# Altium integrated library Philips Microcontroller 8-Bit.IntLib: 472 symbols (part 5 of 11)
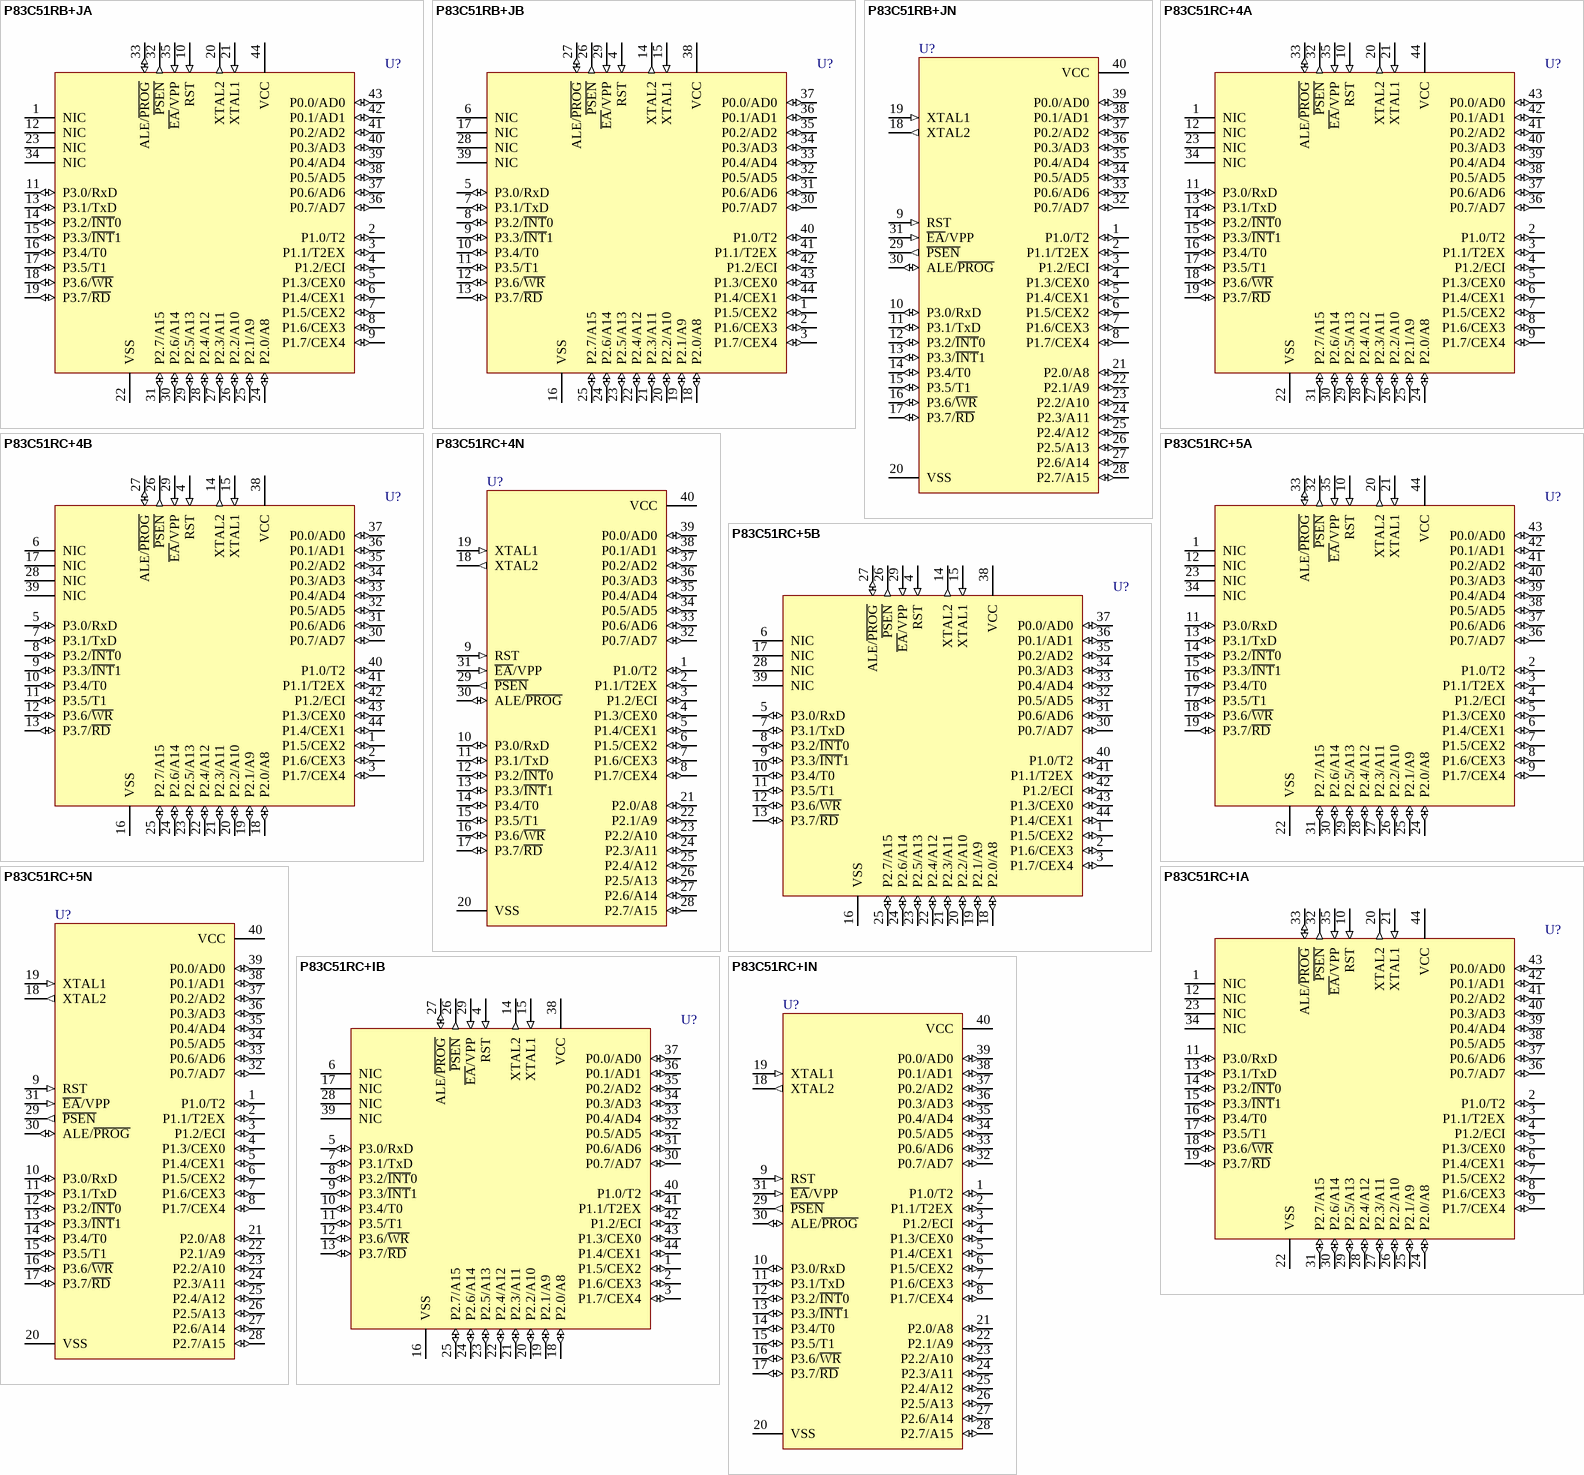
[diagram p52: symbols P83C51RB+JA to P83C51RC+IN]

## P83C51RC+IB
designator U?
80C51 8-Bit Microcontroller Family: 512 B RAM, 32 kB ROM, 5V, Low Power, High Speed
footprint SOT307-2_N (QFP, 44-Leads, Body 10x10mm, Pitch 0.8mm, IPC Medium Density)
footprint SOT307-2_L (QFP, 44-Leads, Body 10x10mm, Pitch 0.8mm, IPC High Density)
footprint SOT307-2_M (QFP, 44-Leads, Body 10x10mm, Pitch 0.8mm, IPC Low Density)
pins: 1 P1.5/CEX2 (io), 2 P1.6/CEX3 (io), 3 P1.7/CEX4 (io), 4 RST (in), 5 P3.0/RxD (io), 6 NIC, 7 P3.1/TxD (io), 8 P3.2/~{INT}0 (io), 9 P3.3/~{INT}1 (io), 10 P3.4/T0 (io), 11 P3.5/T1 (io), 12 P3.6/~{WR} (io), 13 P3.7/~{RD} (io), 14 XTAL2 (out), 15 XTAL1 (in), 16 VSS (power), 17 NIC, 18 P2.0/A8 (io), 19 P2.1/A9 (io), 20 P2.2/A10 (io), 21 P2.3/A11 (io), 22 P2.4/A12 (io), 23 P2.5/A13 (io), 24 P2.6/A14 (io), 25 P2.7/A15 (io), 26 ~{PSEN} (out), 27 ALE/~{PROG} (io), 28 NIC, 29 ~{EA}/VPP (in), 30 P0.7/AD7 (io), 31 P0.6/AD6 (io), 32 P0.5/AD5 (io), 33 P0.4/AD4 (io), 34 P0.3/AD3 (io), 35 P0.2/AD2 (io), 36 P0.1/AD1 (io), 37 P0.0/AD0 (io), 38 VCC (power), 39 NIC, 40 P1.0/T2 (io), 41 P1.1/T2EX (io), 42 P1.2/ECI (io), 43 P1.3/CEX0 (io), 44 P1.4/CEX1 (io)

## P83C51RC+IN
designator U?
80C51 8-Bit Microcontroller Family: 512 B RAM, 32 kB ROM, 5V, Low Power, High Speed
footprint SOT129-1 (DIP, Plastic; 40 Leads; Row Spacing 15.24 mm; Pitch 2.54 mm)
pins: 1 P1.0/T2 (io), 2 P1.1/T2EX (io), 3 P1.2/ECI (io), 4 P1.3/CEX0 (io), 5 P1.4/CEX1 (io), 6 P1.5/CEX2 (io), 7 P1.6/CEX3 (io), 8 P1.7/CEX4 (io), 9 RST (in), 10 P3.0/RxD (io), 11 P3.1/TxD (io), 12 P3.2/~{INT}0 (io), 13 P3.3/~{INT}1 (io), 14 P3.4/T0 (io), 15 P3.5/T1 (io), 16 P3.6/~{WR} (io), 17 P3.7/~{RD} (io), 18 XTAL2 (out), 19 XTAL1 (in), 20 VSS (power), 21 P2.0/A8 (io), 22 P2.1/A9 (io), 23 P2.2/A10 (io), 24 P2.3/A11 (io), 25 P2.4/A12 (io), 26 P2.5/A13 (io), 27 P2.6/A14 (io), 28 P2.7/A15 (io), 29 ~{PSEN} (out), 30 ALE/~{PROG} (io), 31 ~{EA}/VPP (in), 32 P0.7/AD7 (io), 33 P0.6/AD6 (io), 34 P0.5/AD5 (io), 35 P0.4/AD4 (io), 36 P0.3/AD3 (io), 37 P0.2/AD2 (io), 38 P0.1/AD1 (io), 39 P0.0/AD0 (io), 40 VCC (power)

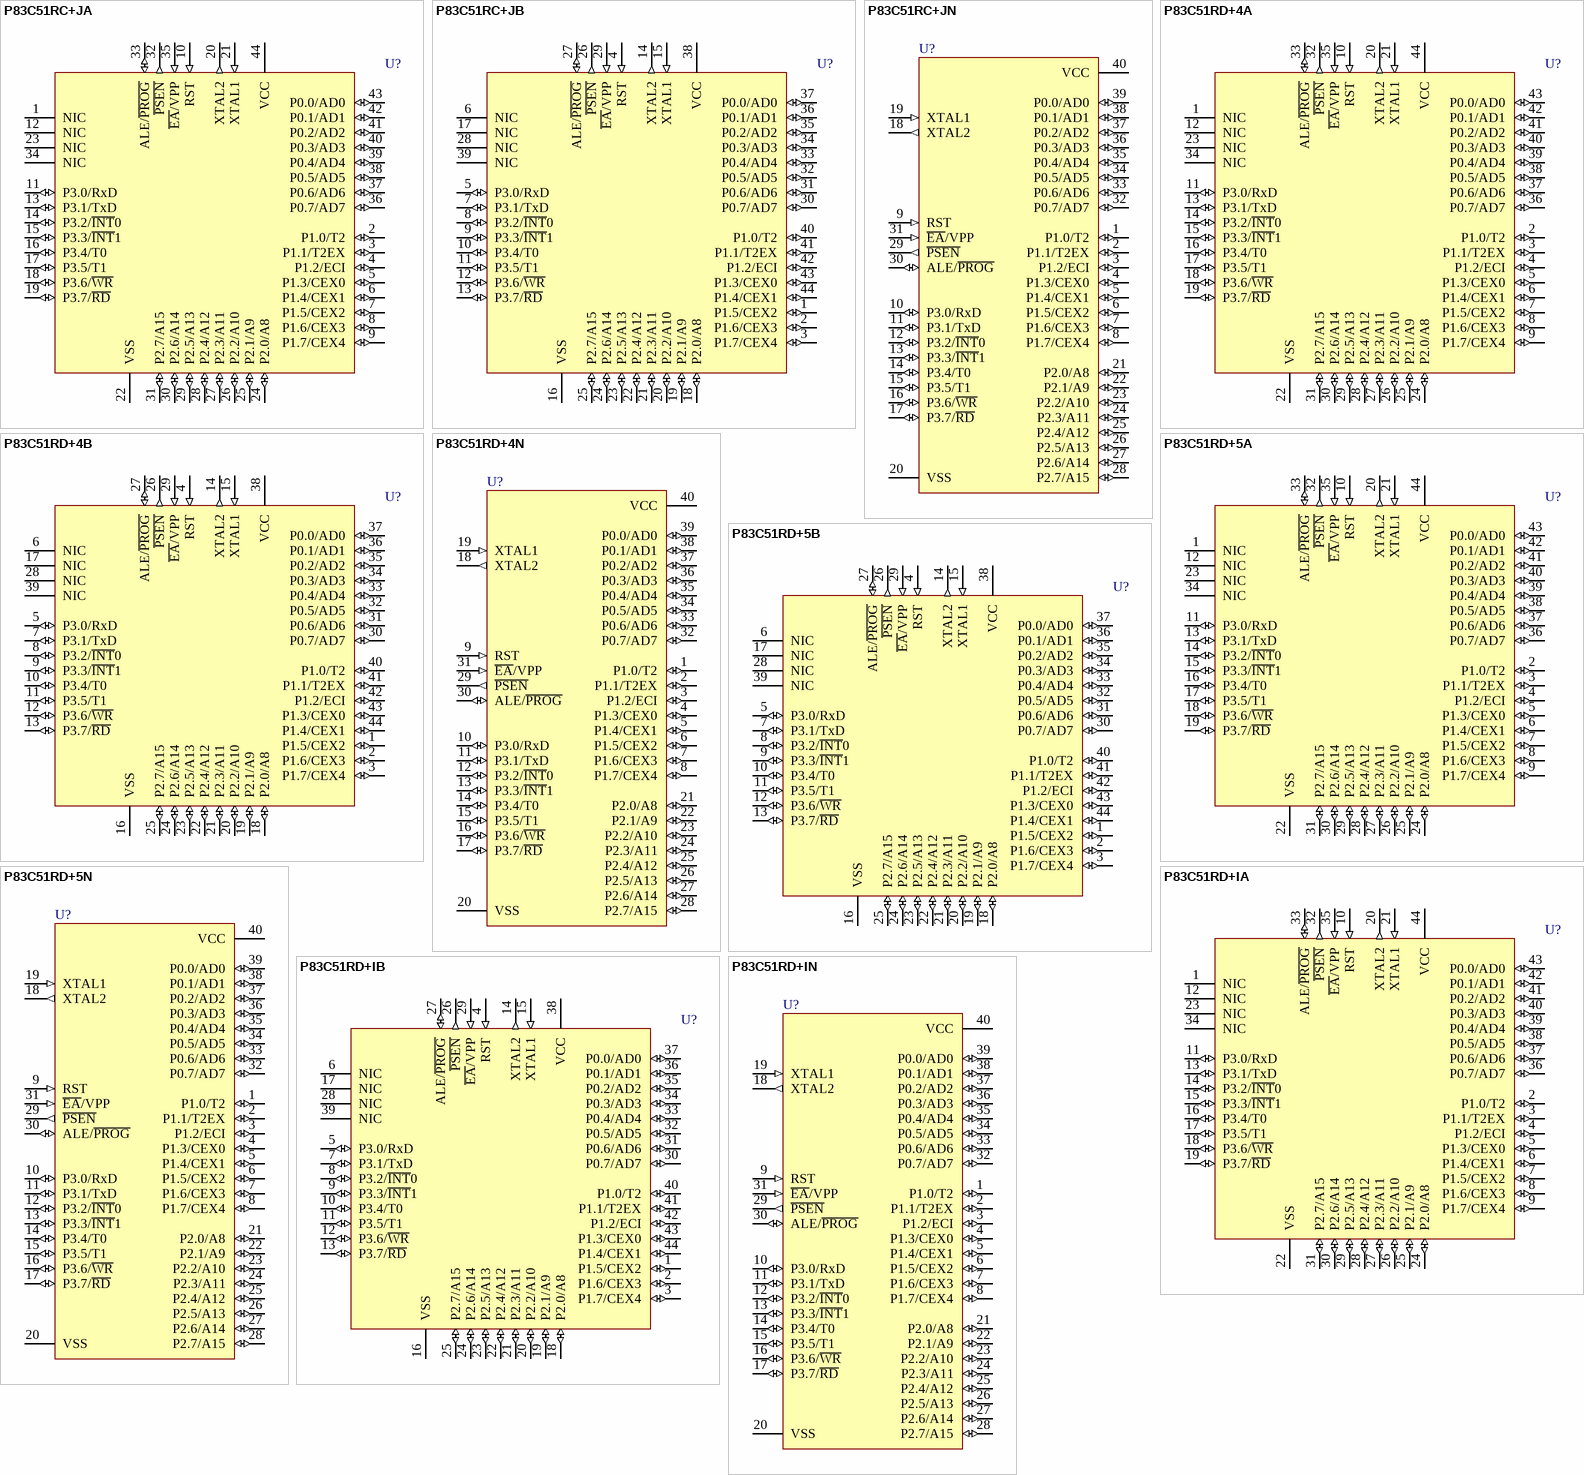
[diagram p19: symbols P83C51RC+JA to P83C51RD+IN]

## P83C51RC+JA
designator U?
80C51 8-Bit Microcontroller Family: 512 B RAM, 32 kB ROM, 5V, Low Power, High Speed
footprint SOT187-2_N (Leaded Chip Carrier, 44-Leads, Body 16.6x16.6mm, Pitch 1.27mm, IPC Medium Density)
footprint SOT187-2_L (Leaded Chip Carrier, 44-Leads, Body 16.6x16.6mm, Pitch 1.27mm, IPC High Density)
footprint SOT187-2_M (Leaded Chip Carrier, 44-Leads, Body 16.6x16.6mm, Pitch 1.27mm, IPC Low Density)
pins: 1 NIC, 2 P1.0/T2 (io), 3 P1.1/T2EX (io), 4 P1.2/ECI (io), 5 P1.3/CEX0 (io), 6 P1.4/CEX1 (io), 7 P1.5/CEX2 (io), 8 P1.6/CEX3 (io), 9 P1.7/CEX4 (io), 10 RST (in), 11 P3.0/RxD (io), 12 NIC, 13 P3.1/TxD (io), 14 P3.2/~{INT}0 (io), 15 P3.3/~{INT}1 (io), 16 P3.4/T0 (io), 17 P3.5/T1 (io), 18 P3.6/~{WR} (io), 19 P3.7/~{RD} (io), 20 XTAL2 (out), 21 XTAL1 (in), 22 VSS (power), 23 NIC, 24 P2.0/A8 (io), 25 P2.1/A9 (io), 26 P2.2/A10 (io), 27 P2.3/A11 (io), 28 P2.4/A12 (io), 29 P2.5/A13 (io), 30 P2.6/A14 (io), 31 P2.7/A15 (io), 32 ~{PSEN} (out), 33 ALE/~{PROG} (io), 34 NIC, 35 ~{EA}/VPP (in), 36 P0.7/AD7 (io), 37 P0.6/AD6 (io), 38 P0.5/AD5 (io), 39 P0.4/AD4 (io), 40 P0.3/AD3 (io), 41 P0.2/AD2 (io), 42 P0.1/AD1 (io), 43 P0.0/AD0 (io), 44 VCC (power)

## P83C51RC+JB
designator U?
80C51 8-Bit Microcontroller Family: 512 B RAM, 32 kB ROM, 5V, Low Power, High Speed
footprint SOT307-2_N (QFP, 44-Leads, Body 10x10mm, Pitch 0.8mm, IPC Medium Density)
footprint SOT307-2_L (QFP, 44-Leads, Body 10x10mm, Pitch 0.8mm, IPC High Density)
footprint SOT307-2_M (QFP, 44-Leads, Body 10x10mm, Pitch 0.8mm, IPC Low Density)
pins: 1 P1.5/CEX2 (io), 2 P1.6/CEX3 (io), 3 P1.7/CEX4 (io), 4 RST (in), 5 P3.0/RxD (io), 6 NIC, 7 P3.1/TxD (io), 8 P3.2/~{INT}0 (io), 9 P3.3/~{INT}1 (io), 10 P3.4/T0 (io), 11 P3.5/T1 (io), 12 P3.6/~{WR} (io), 13 P3.7/~{RD} (io), 14 XTAL2 (out), 15 XTAL1 (in), 16 VSS (power), 17 NIC, 18 P2.0/A8 (io), 19 P2.1/A9 (io), 20 P2.2/A10 (io), 21 P2.3/A11 (io), 22 P2.4/A12 (io), 23 P2.5/A13 (io), 24 P2.6/A14 (io), 25 P2.7/A15 (io), 26 ~{PSEN} (out), 27 ALE/~{PROG} (io), 28 NIC, 29 ~{EA}/VPP (in), 30 P0.7/AD7 (io), 31 P0.6/AD6 (io), 32 P0.5/AD5 (io), 33 P0.4/AD4 (io), 34 P0.3/AD3 (io), 35 P0.2/AD2 (io), 36 P0.1/AD1 (io), 37 P0.0/AD0 (io), 38 VCC (power), 39 NIC, 40 P1.0/T2 (io), 41 P1.1/T2EX (io), 42 P1.2/ECI (io), 43 P1.3/CEX0 (io), 44 P1.4/CEX1 (io)

## P83C51RC+JN
designator U?
80C51 8-Bit Microcontroller Family: 512 B RAM, 32 kB ROM, 5V, Low Power, High Speed
footprint SOT129-1 (DIP, Plastic; 40 Leads; Row Spacing 15.24 mm; Pitch 2.54 mm)
pins: 1 P1.0/T2 (io), 2 P1.1/T2EX (io), 3 P1.2/ECI (io), 4 P1.3/CEX0 (io), 5 P1.4/CEX1 (io), 6 P1.5/CEX2 (io), 7 P1.6/CEX3 (io), 8 P1.7/CEX4 (io), 9 RST (in), 10 P3.0/RxD (io), 11 P3.1/TxD (io), 12 P3.2/~{INT}0 (io), 13 P3.3/~{INT}1 (io), 14 P3.4/T0 (io), 15 P3.5/T1 (io), 16 P3.6/~{WR} (io), 17 P3.7/~{RD} (io), 18 XTAL2 (out), 19 XTAL1 (in), 20 VSS (power), 21 P2.0/A8 (io), 22 P2.1/A9 (io), 23 P2.2/A10 (io), 24 P2.3/A11 (io), 25 P2.4/A12 (io), 26 P2.5/A13 (io), 27 P2.6/A14 (io), 28 P2.7/A15 (io), 29 ~{PSEN} (out), 30 ALE/~{PROG} (io), 31 ~{EA}/VPP (in), 32 P0.7/AD7 (io), 33 P0.6/AD6 (io), 34 P0.5/AD5 (io), 35 P0.4/AD4 (io), 36 P0.3/AD3 (io), 37 P0.2/AD2 (io), 38 P0.1/AD1 (io), 39 P0.0/AD0 (io), 40 VCC (power)

## P83C51RD+4A
designator U?
80C51 8-Bit Microcontroller Family: 1 kB RAM, 64 kB ROM, 2.7V-5.5V, Low Power, High Speed
footprint SOT187-2_N (Leaded Chip Carrier, 44-Leads, Body 16.6x16.6mm, Pitch 1.27mm, IPC Medium Density)
footprint SOT187-2_L (Leaded Chip Carrier, 44-Leads, Body 16.6x16.6mm, Pitch 1.27mm, IPC High Density)
footprint SOT187-2_M (Leaded Chip Carrier, 44-Leads, Body 16.6x16.6mm, Pitch 1.27mm, IPC Low Density)
pins: 1 NIC, 2 P1.0/T2 (io), 3 P1.1/T2EX (io), 4 P1.2/ECI (io), 5 P1.3/CEX0 (io), 6 P1.4/CEX1 (io), 7 P1.5/CEX2 (io), 8 P1.6/CEX3 (io), 9 P1.7/CEX4 (io), 10 RST (in), 11 P3.0/RxD (io), 12 NIC, 13 P3.1/TxD (io), 14 P3.2/~{INT}0 (io), 15 P3.3/~{INT}1 (io), 16 P3.4/T0 (io), 17 P3.5/T1 (io), 18 P3.6/~{WR} (io), 19 P3.7/~{RD} (io), 20 XTAL2 (out), 21 XTAL1 (in), 22 VSS (power), 23 NIC, 24 P2.0/A8 (io), 25 P2.1/A9 (io), 26 P2.2/A10 (io), 27 P2.3/A11 (io), 28 P2.4/A12 (io), 29 P2.5/A13 (io), 30 P2.6/A14 (io), 31 P2.7/A15 (io), 32 ~{PSEN} (out), 33 ALE/~{PROG} (io), 34 NIC, 35 ~{EA}/VPP (in), 36 P0.7/AD7 (io), 37 P0.6/AD6 (io), 38 P0.5/AD5 (io), 39 P0.4/AD4 (io), 40 P0.3/AD3 (io), 41 P0.2/AD2 (io), 42 P0.1/AD1 (io), 43 P0.0/AD0 (io), 44 VCC (power)

## P83C51RD+4B
designator U?
80C51 8-Bit Microcontroller Family: 1 kB RAM, 64 kB ROM, 2.7V-5.5V, Low Power, High Speed
footprint SOT307-2_N (QFP, 44-Leads, Body 10x10mm, Pitch 0.8mm, IPC Medium Density)
footprint SOT307-2_L (QFP, 44-Leads, Body 10x10mm, Pitch 0.8mm, IPC High Density)
footprint SOT307-2_M (QFP, 44-Leads, Body 10x10mm, Pitch 0.8mm, IPC Low Density)
pins: 1 P1.5/CEX2 (io), 2 P1.6/CEX3 (io), 3 P1.7/CEX4 (io), 4 RST (in), 5 P3.0/RxD (io), 6 NIC, 7 P3.1/TxD (io), 8 P3.2/~{INT}0 (io), 9 P3.3/~{INT}1 (io), 10 P3.4/T0 (io), 11 P3.5/T1 (io), 12 P3.6/~{WR} (io), 13 P3.7/~{RD} (io), 14 XTAL2 (out), 15 XTAL1 (in), 16 VSS (power), 17 NIC, 18 P2.0/A8 (io), 19 P2.1/A9 (io), 20 P2.2/A10 (io), 21 P2.3/A11 (io), 22 P2.4/A12 (io), 23 P2.5/A13 (io), 24 P2.6/A14 (io), 25 P2.7/A15 (io), 26 ~{PSEN} (out), 27 ALE/~{PROG} (io), 28 NIC, 29 ~{EA}/VPP (in), 30 P0.7/AD7 (io), 31 P0.6/AD6 (io), 32 P0.5/AD5 (io), 33 P0.4/AD4 (io), 34 P0.3/AD3 (io), 35 P0.2/AD2 (io), 36 P0.1/AD1 (io), 37 P0.0/AD0 (io), 38 VCC (power), 39 NIC, 40 P1.0/T2 (io), 41 P1.1/T2EX (io), 42 P1.2/ECI (io), 43 P1.3/CEX0 (io), 44 P1.4/CEX1 (io)

## P83C51RD+4N
designator U?
80C51 8-Bit Microcontroller Family: 1 kB RAM, 64 kB ROM, 2.7V-5.5V, Low Power, High Speed
footprint SOT129-1 (DIP, Plastic; 40 Leads; Row Spacing 15.24 mm; Pitch 2.54 mm)
pins: 1 P1.0/T2 (io), 2 P1.1/T2EX (io), 3 P1.2/ECI (io), 4 P1.3/CEX0 (io), 5 P1.4/CEX1 (io), 6 P1.5/CEX2 (io), 7 P1.6/CEX3 (io), 8 P1.7/CEX4 (io), 9 RST (in), 10 P3.0/RxD (io), 11 P3.1/TxD (io), 12 P3.2/~{INT}0 (io), 13 P3.3/~{INT}1 (io), 14 P3.4/T0 (io), 15 P3.5/T1 (io), 16 P3.6/~{WR} (io), 17 P3.7/~{RD} (io), 18 XTAL2 (out), 19 XTAL1 (in), 20 VSS (power), 21 P2.0/A8 (io), 22 P2.1/A9 (io), 23 P2.2/A10 (io), 24 P2.3/A11 (io), 25 P2.4/A12 (io), 26 P2.5/A13 (io), 27 P2.6/A14 (io), 28 P2.7/A15 (io), 29 ~{PSEN} (out), 30 ALE/~{PROG} (io), 31 ~{EA}/VPP (in), 32 P0.7/AD7 (io), 33 P0.6/AD6 (io), 34 P0.5/AD5 (io), 35 P0.4/AD4 (io), 36 P0.3/AD3 (io), 37 P0.2/AD2 (io), 38 P0.1/AD1 (io), 39 P0.0/AD0 (io), 40 VCC (power)

## P83C51RD+5A
designator U?
80C51 8-Bit Microcontroller Family: 1 kB RAM, 64 kB ROM, 2.7V-5.5V, Low Power, High Speed
footprint SOT187-2_N (Leaded Chip Carrier, 44-Leads, Body 16.6x16.6mm, Pitch 1.27mm, IPC Medium Density)
footprint SOT187-2_L (Leaded Chip Carrier, 44-Leads, Body 16.6x16.6mm, Pitch 1.27mm, IPC High Density)
footprint SOT187-2_M (Leaded Chip Carrier, 44-Leads, Body 16.6x16.6mm, Pitch 1.27mm, IPC Low Density)
pins: 1 NIC, 2 P1.0/T2 (io), 3 P1.1/T2EX (io), 4 P1.2/ECI (io), 5 P1.3/CEX0 (io), 6 P1.4/CEX1 (io), 7 P1.5/CEX2 (io), 8 P1.6/CEX3 (io), 9 P1.7/CEX4 (io), 10 RST (in), 11 P3.0/RxD (io), 12 NIC, 13 P3.1/TxD (io), 14 P3.2/~{INT}0 (io), 15 P3.3/~{INT}1 (io), 16 P3.4/T0 (io), 17 P3.5/T1 (io), 18 P3.6/~{WR} (io), 19 P3.7/~{RD} (io), 20 XTAL2 (out), 21 XTAL1 (in), 22 VSS (power), 23 NIC, 24 P2.0/A8 (io), 25 P2.1/A9 (io), 26 P2.2/A10 (io), 27 P2.3/A11 (io), 28 P2.4/A12 (io), 29 P2.5/A13 (io), 30 P2.6/A14 (io), 31 P2.7/A15 (io), 32 ~{PSEN} (out), 33 ALE/~{PROG} (io), 34 NIC, 35 ~{EA}/VPP (in), 36 P0.7/AD7 (io), 37 P0.6/AD6 (io), 38 P0.5/AD5 (io), 39 P0.4/AD4 (io), 40 P0.3/AD3 (io), 41 P0.2/AD2 (io), 42 P0.1/AD1 (io), 43 P0.0/AD0 (io), 44 VCC (power)

## P83C51RD+5B
designator U?
80C51 8-Bit Microcontroller Family: 1 kB RAM, 64 kB ROM, 2.7V-5.5V, Low Power, High Speed
footprint SOT307-2_N (QFP, 44-Leads, Body 10x10mm, Pitch 0.8mm, IPC Medium Density)
footprint SOT307-2_L (QFP, 44-Leads, Body 10x10mm, Pitch 0.8mm, IPC High Density)
footprint SOT307-2_M (QFP, 44-Leads, Body 10x10mm, Pitch 0.8mm, IPC Low Density)
pins: 1 P1.5/CEX2 (io), 2 P1.6/CEX3 (io), 3 P1.7/CEX4 (io), 4 RST (in), 5 P3.0/RxD (io), 6 NIC, 7 P3.1/TxD (io), 8 P3.2/~{INT}0 (io), 9 P3.3/~{INT}1 (io), 10 P3.4/T0 (io), 11 P3.5/T1 (io), 12 P3.6/~{WR} (io), 13 P3.7/~{RD} (io), 14 XTAL2 (out), 15 XTAL1 (in), 16 VSS (power), 17 NIC, 18 P2.0/A8 (io), 19 P2.1/A9 (io), 20 P2.2/A10 (io), 21 P2.3/A11 (io), 22 P2.4/A12 (io), 23 P2.5/A13 (io), 24 P2.6/A14 (io), 25 P2.7/A15 (io), 26 ~{PSEN} (out), 27 ALE/~{PROG} (io), 28 NIC, 29 ~{EA}/VPP (in), 30 P0.7/AD7 (io), 31 P0.6/AD6 (io), 32 P0.5/AD5 (io), 33 P0.4/AD4 (io), 34 P0.3/AD3 (io), 35 P0.2/AD2 (io), 36 P0.1/AD1 (io), 37 P0.0/AD0 (io), 38 VCC (power), 39 NIC, 40 P1.0/T2 (io), 41 P1.1/T2EX (io), 42 P1.2/ECI (io), 43 P1.3/CEX0 (io), 44 P1.4/CEX1 (io)

## P83C51RD+5N
designator U?
80C51 8-Bit Microcontroller Family: 1 kB RAM, 64 kB ROM, 2.7V-5.5V, Low Power, High Speed
footprint SOT129-1 (DIP, Plastic; 40 Leads; Row Spacing 15.24 mm; Pitch 2.54 mm)
pins: 1 P1.0/T2 (io), 2 P1.1/T2EX (io), 3 P1.2/ECI (io), 4 P1.3/CEX0 (io), 5 P1.4/CEX1 (io), 6 P1.5/CEX2 (io), 7 P1.6/CEX3 (io), 8 P1.7/CEX4 (io), 9 RST (in), 10 P3.0/RxD (io), 11 P3.1/TxD (io), 12 P3.2/~{INT}0 (io), 13 P3.3/~{INT}1 (io), 14 P3.4/T0 (io), 15 P3.5/T1 (io), 16 P3.6/~{WR} (io), 17 P3.7/~{RD} (io), 18 XTAL2 (out), 19 XTAL1 (in), 20 VSS (power), 21 P2.0/A8 (io), 22 P2.1/A9 (io), 23 P2.2/A10 (io), 24 P2.3/A11 (io), 25 P2.4/A12 (io), 26 P2.5/A13 (io), 27 P2.6/A14 (io), 28 P2.7/A15 (io), 29 ~{PSEN} (out), 30 ALE/~{PROG} (io), 31 ~{EA}/VPP (in), 32 P0.7/AD7 (io), 33 P0.6/AD6 (io), 34 P0.5/AD5 (io), 35 P0.4/AD4 (io), 36 P0.3/AD3 (io), 37 P0.2/AD2 (io), 38 P0.1/AD1 (io), 39 P0.0/AD0 (io), 40 VCC (power)

## P83C51RD+IA
designator U?
80C51 8-Bit Microcontroller Family: 1 kB RAM, 64 kB ROM, 5V, Low Power, High Speed
footprint SOT187-2_N (Leaded Chip Carrier, 44-Leads, Body 16.6x16.6mm, Pitch 1.27mm, IPC Medium Density)
footprint SOT187-2_L (Leaded Chip Carrier, 44-Leads, Body 16.6x16.6mm, Pitch 1.27mm, IPC High Density)
footprint SOT187-2_M (Leaded Chip Carrier, 44-Leads, Body 16.6x16.6mm, Pitch 1.27mm, IPC Low Density)
pins: 1 NIC, 2 P1.0/T2 (io), 3 P1.1/T2EX (io), 4 P1.2/ECI (io), 5 P1.3/CEX0 (io), 6 P1.4/CEX1 (io), 7 P1.5/CEX2 (io), 8 P1.6/CEX3 (io), 9 P1.7/CEX4 (io), 10 RST (in), 11 P3.0/RxD (io), 12 NIC, 13 P3.1/TxD (io), 14 P3.2/~{INT}0 (io), 15 P3.3/~{INT}1 (io), 16 P3.4/T0 (io), 17 P3.5/T1 (io), 18 P3.6/~{WR} (io), 19 P3.7/~{RD} (io), 20 XTAL2 (out), 21 XTAL1 (in), 22 VSS (power), 23 NIC, 24 P2.0/A8 (io), 25 P2.1/A9 (io), 26 P2.2/A10 (io), 27 P2.3/A11 (io), 28 P2.4/A12 (io), 29 P2.5/A13 (io), 30 P2.6/A14 (io), 31 P2.7/A15 (io), 32 ~{PSEN} (out), 33 ALE/~{PROG} (io), 34 NIC, 35 ~{EA}/VPP (in), 36 P0.7/AD7 (io), 37 P0.6/AD6 (io), 38 P0.5/AD5 (io), 39 P0.4/AD4 (io), 40 P0.3/AD3 (io), 41 P0.2/AD2 (io), 42 P0.1/AD1 (io), 43 P0.0/AD0 (io), 44 VCC (power)

## P83C51RD+IB
designator U?
80C51 8-Bit Microcontroller Family: 1 kB RAM, 64 kB ROM, 5V, Low Power, High Speed
footprint SOT307-2_N (QFP, 44-Leads, Body 10x10mm, Pitch 0.8mm, IPC Medium Density)
footprint SOT307-2_L (QFP, 44-Leads, Body 10x10mm, Pitch 0.8mm, IPC High Density)
footprint SOT307-2_M (QFP, 44-Leads, Body 10x10mm, Pitch 0.8mm, IPC Low Density)
pins: 1 P1.5/CEX2 (io), 2 P1.6/CEX3 (io), 3 P1.7/CEX4 (io), 4 RST (in), 5 P3.0/RxD (io), 6 NIC, 7 P3.1/TxD (io), 8 P3.2/~{INT}0 (io), 9 P3.3/~{INT}1 (io), 10 P3.4/T0 (io), 11 P3.5/T1 (io), 12 P3.6/~{WR} (io), 13 P3.7/~{RD} (io), 14 XTAL2 (out), 15 XTAL1 (in), 16 VSS (power), 17 NIC, 18 P2.0/A8 (io), 19 P2.1/A9 (io), 20 P2.2/A10 (io), 21 P2.3/A11 (io), 22 P2.4/A12 (io), 23 P2.5/A13 (io), 24 P2.6/A14 (io), 25 P2.7/A15 (io), 26 ~{PSEN} (out), 27 ALE/~{PROG} (io), 28 NIC, 29 ~{EA}/VPP (in), 30 P0.7/AD7 (io), 31 P0.6/AD6 (io), 32 P0.5/AD5 (io), 33 P0.4/AD4 (io), 34 P0.3/AD3 (io), 35 P0.2/AD2 (io), 36 P0.1/AD1 (io), 37 P0.0/AD0 (io), 38 VCC (power), 39 NIC, 40 P1.0/T2 (io), 41 P1.1/T2EX (io), 42 P1.2/ECI (io), 43 P1.3/CEX0 (io), 44 P1.4/CEX1 (io)

## P83C51RD+IN
designator U?
80C51 8-Bit Microcontroller Family: 1 kB RAM, 64 kB ROM, 5V, Low Power, High Speed
footprint SOT129-1 (DIP, Plastic; 40 Leads; Row Spacing 15.24 mm; Pitch 2.54 mm)
pins: 1 P1.0/T2 (io), 2 P1.1/T2EX (io), 3 P1.2/ECI (io), 4 P1.3/CEX0 (io), 5 P1.4/CEX1 (io), 6 P1.5/CEX2 (io), 7 P1.6/CEX3 (io), 8 P1.7/CEX4 (io), 9 RST (in), 10 P3.0/RxD (io), 11 P3.1/TxD (io), 12 P3.2/~{INT}0 (io), 13 P3.3/~{INT}1 (io), 14 P3.4/T0 (io), 15 P3.5/T1 (io), 16 P3.6/~{WR} (io), 17 P3.7/~{RD} (io), 18 XTAL2 (out), 19 XTAL1 (in), 20 VSS (power), 21 P2.0/A8 (io), 22 P2.1/A9 (io), 23 P2.2/A10 (io), 24 P2.3/A11 (io), 25 P2.4/A12 (io), 26 P2.5/A13 (io), 27 P2.6/A14 (io), 28 P2.7/A15 (io), 29 ~{PSEN} (out), 30 ALE/~{PROG} (io), 31 ~{EA}/VPP (in), 32 P0.7/AD7 (io), 33 P0.6/AD6 (io), 34 P0.5/AD5 (io), 35 P0.4/AD4 (io), 36 P0.3/AD3 (io), 37 P0.2/AD2 (io), 38 P0.1/AD1 (io), 39 P0.0/AD0 (io), 40 VCC (power)

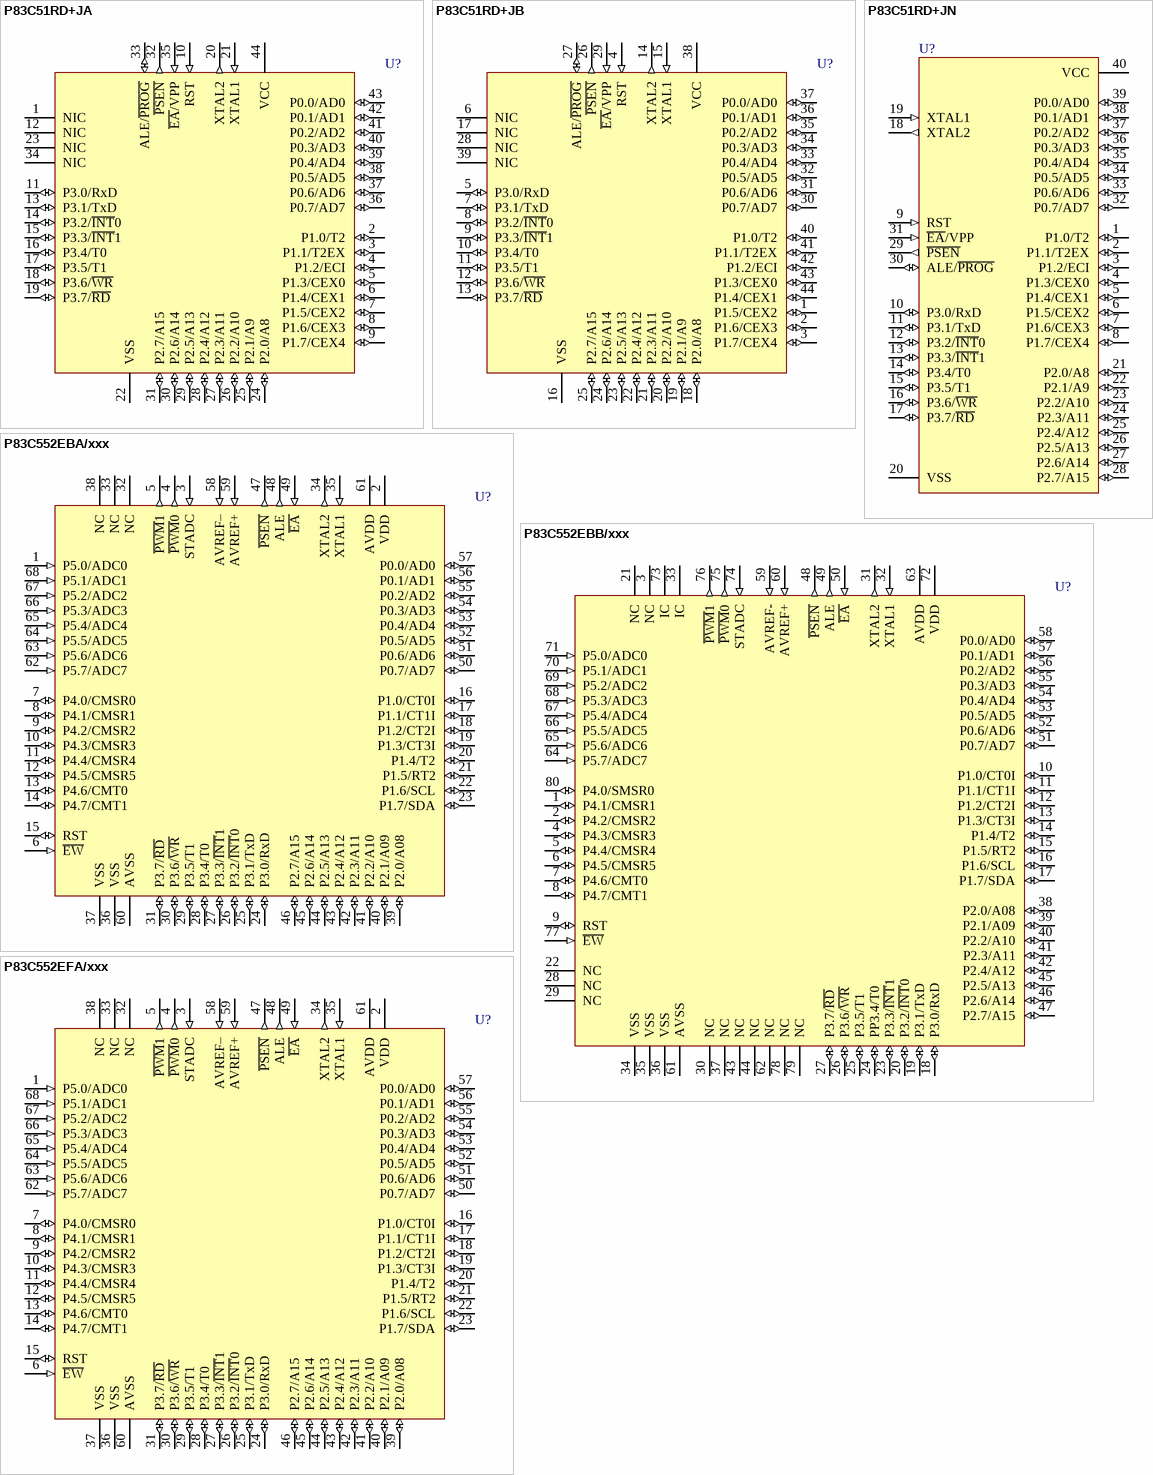
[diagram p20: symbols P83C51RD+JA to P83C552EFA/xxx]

## P83C51RD+JA
designator U?
80C51 8-Bit Microcontroller Family: 1 kB RAM, 64 kB ROM, 5V, Low Power, High Speed
footprint SOT187-2_N (Leaded Chip Carrier, 44-Leads, Body 16.6x16.6mm, Pitch 1.27mm, IPC Medium Density)
footprint SOT187-2_L (Leaded Chip Carrier, 44-Leads, Body 16.6x16.6mm, Pitch 1.27mm, IPC High Density)
footprint SOT187-2_M (Leaded Chip Carrier, 44-Leads, Body 16.6x16.6mm, Pitch 1.27mm, IPC Low Density)
pins: 1 NIC, 2 P1.0/T2 (io), 3 P1.1/T2EX (io), 4 P1.2/ECI (io), 5 P1.3/CEX0 (io), 6 P1.4/CEX1 (io), 7 P1.5/CEX2 (io), 8 P1.6/CEX3 (io), 9 P1.7/CEX4 (io), 10 RST (in), 11 P3.0/RxD (io), 12 NIC, 13 P3.1/TxD (io), 14 P3.2/~{INT}0 (io), 15 P3.3/~{INT}1 (io), 16 P3.4/T0 (io), 17 P3.5/T1 (io), 18 P3.6/~{WR} (io), 19 P3.7/~{RD} (io), 20 XTAL2 (out), 21 XTAL1 (in), 22 VSS (power), 23 NIC, 24 P2.0/A8 (io), 25 P2.1/A9 (io), 26 P2.2/A10 (io), 27 P2.3/A11 (io), 28 P2.4/A12 (io), 29 P2.5/A13 (io), 30 P2.6/A14 (io), 31 P2.7/A15 (io), 32 ~{PSEN} (out), 33 ALE/~{PROG} (io), 34 NIC, 35 ~{EA}/VPP (in), 36 P0.7/AD7 (io), 37 P0.6/AD6 (io), 38 P0.5/AD5 (io), 39 P0.4/AD4 (io), 40 P0.3/AD3 (io), 41 P0.2/AD2 (io), 42 P0.1/AD1 (io), 43 P0.0/AD0 (io), 44 VCC (power)

## P83C51RD+JB
designator U?
80C51 8-Bit Microcontroller Family: 1 kB RAM, 64 kB ROM, 5V, Low Power, High Speed
footprint SOT307-2_N (QFP, 44-Leads, Body 10x10mm, Pitch 0.8mm, IPC Medium Density)
footprint SOT307-2_L (QFP, 44-Leads, Body 10x10mm, Pitch 0.8mm, IPC High Density)
footprint SOT307-2_M (QFP, 44-Leads, Body 10x10mm, Pitch 0.8mm, IPC Low Density)
pins: 1 P1.5/CEX2 (io), 2 P1.6/CEX3 (io), 3 P1.7/CEX4 (io), 4 RST (in), 5 P3.0/RxD (io), 6 NIC, 7 P3.1/TxD (io), 8 P3.2/~{INT}0 (io), 9 P3.3/~{INT}1 (io), 10 P3.4/T0 (io), 11 P3.5/T1 (io), 12 P3.6/~{WR} (io), 13 P3.7/~{RD} (io), 14 XTAL2 (out), 15 XTAL1 (in), 16 VSS (power), 17 NIC, 18 P2.0/A8 (io), 19 P2.1/A9 (io), 20 P2.2/A10 (io), 21 P2.3/A11 (io), 22 P2.4/A12 (io), 23 P2.5/A13 (io), 24 P2.6/A14 (io), 25 P2.7/A15 (io), 26 ~{PSEN} (out), 27 ALE/~{PROG} (io), 28 NIC, 29 ~{EA}/VPP (in), 30 P0.7/AD7 (io), 31 P0.6/AD6 (io), 32 P0.5/AD5 (io), 33 P0.4/AD4 (io), 34 P0.3/AD3 (io), 35 P0.2/AD2 (io), 36 P0.1/AD1 (io), 37 P0.0/AD0 (io), 38 VCC (power), 39 NIC, 40 P1.0/T2 (io), 41 P1.1/T2EX (io), 42 P1.2/ECI (io), 43 P1.3/CEX0 (io), 44 P1.4/CEX1 (io)

## P83C51RD+JN
designator U?
80C51 8-Bit Microcontroller Family: 1 kB RAM, 64 kB ROM, 5V, Low Power, High Speed
footprint SOT129-1 (DIP, Plastic; 40 Leads; Row Spacing 15.24 mm; Pitch 2.54 mm)
pins: 1 P1.0/T2 (io), 2 P1.1/T2EX (io), 3 P1.2/ECI (io), 4 P1.3/CEX0 (io), 5 P1.4/CEX1 (io), 6 P1.5/CEX2 (io), 7 P1.6/CEX3 (io), 8 P1.7/CEX4 (io), 9 RST (in), 10 P3.0/RxD (io), 11 P3.1/TxD (io), 12 P3.2/~{INT}0 (io), 13 P3.3/~{INT}1 (io), 14 P3.4/T0 (io), 15 P3.5/T1 (io), 16 P3.6/~{WR} (io), 17 P3.7/~{RD} (io), 18 XTAL2 (out), 19 XTAL1 (in), 20 VSS (power), 21 P2.0/A8 (io), 22 P2.1/A9 (io), 23 P2.2/A10 (io), 24 P2.3/A11 (io), 25 P2.4/A12 (io), 26 P2.5/A13 (io), 27 P2.6/A14 (io), 28 P2.7/A15 (io), 29 ~{PSEN} (out), 30 ALE/~{PROG} (io), 31 ~{EA}/VPP (in), 32 P0.7/AD7 (io), 33 P0.6/AD6 (io), 34 P0.5/AD5 (io), 35 P0.4/AD4 (io), 36 P0.3/AD3 (io), 37 P0.2/AD2 (io), 38 P0.1/AD1 (io), 39 P0.0/AD0 (io), 40 VCC (power)

## P83C552EBA/xxx
designator U?
8k Mask Programmable ROM, Single-Chip 8-Bit Microcontroller with 10-bit A/D, Capture/Compare Timer, High-Speed Outputs, PWM
footprint SOT188-2_N (Leaded Chip Carrier, 68-Leads, Body 24.2x24.2mm, Pitch 1.27mm, IPC Medium Density)
footprint SOT188-2_L (Leaded Chip Carrier, 68-Leads, Body 24.2x24.2mm, Pitch 1.27mm, IPC High Density)
footprint SOT188-2_M (Leaded Chip Carrier, 68-Leads, Body 24.2x24.2mm, Pitch 1.27mm, IPC Low Density)
pins: 1 P5.0/ADC0 (in), 2 VDD (power), 3 STADC (in), 4 ~{PWM}0 (out), 5 ~{PWM}1 (out), 6 ~{EW} (in), 7 P4.0/CMSR0 (io), 8 P4.1/CMSR1 (io), 9 P4.2/CMSR2 (io), 10 P4.3/CMSR3 (io), 11 P4.4/CMSR4 (io), 12 P4.5/CMSR5 (io), 13 P4.6/CMT0 (io), 14 P4.7/CMT1 (io), 15 RST (io), 16 P1.0/CT0I (io), 17 P1.1/CT1I (io), 18 P1.2/CT2I (io), 19 P1.3/CT3I (io), 20 P1.4/T2 (io), 21 P1.5/RT2 (io), 22 P1.6/SCL (io), 23 P1.7/SDA (io), 24 P3.0/RxD (io), 25 P3.1/TxD (io), 26 P3.2/~{INT}0 (io), 27 P3.3/~{INT}1 (io), 28 P3.4/T0 (io), 29 P3.5/T1 (io), 30 P3.6/~{WR} (io), 31 P3.7/~{RD} (io), 32 NC, 33 NC, 34 XTAL2 (out), 35 XTAL1 (in), 36 VSS (power), 37 VSS (power), 38 NC, 39 P2.0/A08 (io), 40 P2.1/A09 (io), 41 P2.2/A10 (io), 42 P2.3/A11 (io), 43 P2.4/A12 (io), 44 P2.5/A13 (io), 45 P2.6/A14 (io), 46 P2.7/A15 (io), 47 ~{PSEN} (out), 48 ALE (out), 49 ~{EA} (in), 50 P0.7/AD7 (io), 51 P0.6/AD6 (io), 52 P0.5/AD5 (io), 53 P0.4/AD4 (io), 54 P0.3/AD3 (io), 55 P0.2/AD2 (io), 56 P0.1/AD1 (io), 57 P0.0/AD0 (io), 58 AVREF– (in), 59 AVREF+ (in), 60 AVSS (power), 61 AVDD (power), 62 P5.7/ADC7 (in), 63 P5.6/ADC6 (in), 64 P5.5/ADC5 (in), 65 P5.4/ADC4 (in), 66 P5.3/ADC3 (in), 67 P5.2/ADC2 (in), 68 P5.1/ADC1 (in)

## P83C552EBB/xxx
designator U?
8k Mask Programmable ROM, Single-Chip 8-Bit Microcontroller with 10-bit A/D, Capture/Compare Timer, High-Speed Outputs, PWM; DoNotConnect: Pins 33 & 73 are internally connected (IC), do not use.
footprint SOT318-2_N (QFP, 80-Leads, Body 20x14mm, Pitch 0.8mm, IPC Medium Density)
footprint SOT318-2_L (QFP, 80-Leads, Body 20x14mm, Pitch 0.8mm, IPC High Density)
footprint SOT318-2_M (QFP, 80-Leads, Body 20x14mm, Pitch 0.8mm, IPC Low Density)
pins: 1 P4.1/CMSR1 (io), 2 P4.2/CMSR2 (io), 3 NC, 4 P4.3/CMSR3 (io), 5 P4.4/CMSR4 (io), 6 P4.5/CMSR5 (io), 7 P4.6/CMT0 (io), 8 P4.7/CMT1 (io), 9 RST (io), 10 P1.0/CT0I (io), 11 P1.1/CT1I (io), 12 P1.2/CT2I (io), 13 P1.3/CT3I (io), 14 P1.4/T2 (io), 15 P1.5/RT2 (io), 16 P1.6/SCL (io), 17 P1.7/SDA (io), 18 P3.0/RxD (io), 19 P3.1/TxD (io), 20 P3.2/~{INT}0 (io), 21 NC, 22 NC, 23 P3.3/~{INT}1 (io), 24 PP3.4/T0 (io), 25 P3.5/T1 (io), 26 P3.6/~{WR} (io), 27 P3.7/~{RD} (io), 28 NC, 29 NC, 30 NC, 31 XTAL2 (out), 32 XTAL1 (in), 33 IC, 34 VSS (power), 35 VSS (power), 36 VSS (power), 37 NC, 38 P2.0/A08 (io), 39 P2.1/A09 (io), 40 P2.2/A10 (io), 41 P2.3/A11 (io), 42 P2.4/A12 (io), 43 NC, 44 NC, 45 P2.5/A13 (io), 46 P2.6/A14 (io), 47 P2.7/A15 (io), 48 ~{PSEN} (out), 49 ALE (out), 50 ~{EA} (in), 51 P0.7/AD7 (io), 52 P0.6/AD6 (io), 53 P0.5/AD5 (io), 54 P0.4/AD4 (io), 55 P0.3/AD3 (io), 56 P0.2/AD2 (io), 57 P0.1/AD1 (io), 58 P0.0/AD0 (io), 59 AVREF- (in), 60 AVREF+ (in), 61 AVSS (power), 62 NC, 63 AVDD (power), 64 P5.7/ADC7 (in), 65 P5.6/ADC6 (in), 66 P5.5/ADC5 (in), 67 P5.4/ADC4 (in), 68 P5.3/ADC3 (in), 69 P5.2/ADC2 (in), 70 P5.1/ADC1 (in), 71 P5.0/ADC0 (in), 72 VDD (power), 73 IC, 74 STADC (in), 75 ~{PWM}0 (out), 76 ~{PWM}1 (out), 77 ~{EW} (in), 78 NC, 79 NC, 80 P4.0/SMSR0 (io)

## P83C552EFA/xxx
designator U?
8k Mask Programmable ROM, Single-Chip 8-Bit Microcontroller with 10-bit A/D, Capture/Compare Timer, High-Speed Outputs, PWM
footprint SOT188-2_N (Leaded Chip Carrier, 68-Leads, Body 24.2x24.2mm, Pitch 1.27mm, IPC Medium Density)
footprint SOT188-2_L (Leaded Chip Carrier, 68-Leads, Body 24.2x24.2mm, Pitch 1.27mm, IPC High Density)
footprint SOT188-2_M (Leaded Chip Carrier, 68-Leads, Body 24.2x24.2mm, Pitch 1.27mm, IPC Low Density)
pins: 1 P5.0/ADC0 (in), 2 VDD (power), 3 STADC (in), 4 ~{PWM}0 (out), 5 ~{PWM}1 (out), 6 ~{EW} (in), 7 P4.0/CMSR0 (io), 8 P4.1/CMSR1 (io), 9 P4.2/CMSR2 (io), 10 P4.3/CMSR3 (io), 11 P4.4/CMSR4 (io), 12 P4.5/CMSR5 (io), 13 P4.6/CMT0 (io), 14 P4.7/CMT1 (io), 15 RST (io), 16 P1.0/CT0I (io), 17 P1.1/CT1I (io), 18 P1.2/CT2I (io), 19 P1.3/CT3I (io), 20 P1.4/T2 (io), 21 P1.5/RT2 (io), 22 P1.6/SCL (io), 23 P1.7/SDA (io), 24 P3.0/RxD (io), 25 P3.1/TxD (io), 26 P3.2/~{INT}0 (io), 27 P3.3/~{INT}1 (io), 28 P3.4/T0 (io), 29 P3.5/T1 (io), 30 P3.6/~{WR} (io), 31 P3.7/~{RD} (io), 32 NC, 33 NC, 34 XTAL2 (out), 35 XTAL1 (in), 36 VSS (power), 37 VSS (power), 38 NC, 39 P2.0/A08 (io), 40 P2.1/A09 (io), 41 P2.2/A10 (io), 42 P2.3/A11 (io), 43 P2.4/A12 (io), 44 P2.5/A13 (io), 45 P2.6/A14 (io), 46 P2.7/A15 (io), 47 ~{PSEN} (out), 48 ALE (out), 49 ~{EA} (in), 50 P0.7/AD7 (io), 51 P0.6/AD6 (io), 52 P0.5/AD5 (io), 53 P0.4/AD4 (io), 54 P0.3/AD3 (io), 55 P0.2/AD2 (io), 56 P0.1/AD1 (io), 57 P0.0/AD0 (io), 58 AVREF– (in), 59 AVREF+ (in), 60 AVSS (power), 61 AVDD (power), 62 P5.7/ADC7 (in), 63 P5.6/ADC6 (in), 64 P5.5/ADC5 (in), 65 P5.4/ADC4 (in), 66 P5.3/ADC3 (in), 67 P5.2/ADC2 (in), 68 P5.1/ADC1 (in)

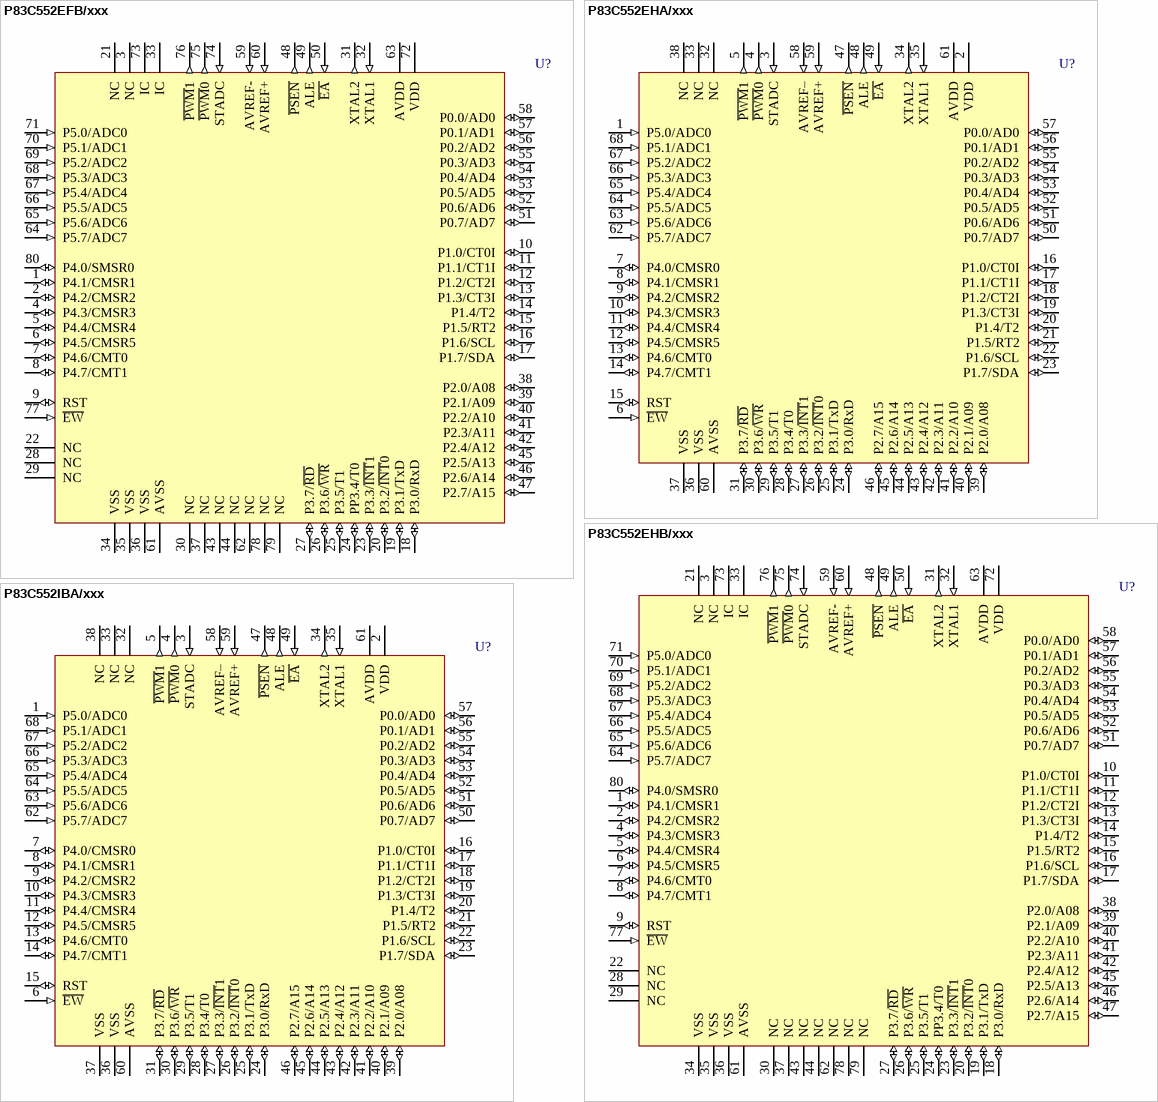
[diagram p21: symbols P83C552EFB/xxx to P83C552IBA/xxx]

## P83C552EFB/xxx
designator U?
8k Mask Programmable ROM, Single-Chip 8-Bit Microcontroller with 10-bit A/D, Capture/Compare Timer, High-Speed Outputs, PWM; DoNotConnect: Pins 33 & 73 are internally connected (IC), do not use.
footprint SOT318-2_N (QFP, 80-Leads, Body 20x14mm, Pitch 0.8mm, IPC Medium Density)
footprint SOT318-2_L (QFP, 80-Leads, Body 20x14mm, Pitch 0.8mm, IPC High Density)
footprint SOT318-2_M (QFP, 80-Leads, Body 20x14mm, Pitch 0.8mm, IPC Low Density)
pins: 1 P4.1/CMSR1 (io), 2 P4.2/CMSR2 (io), 3 NC, 4 P4.3/CMSR3 (io), 5 P4.4/CMSR4 (io), 6 P4.5/CMSR5 (io), 7 P4.6/CMT0 (io), 8 P4.7/CMT1 (io), 9 RST (io), 10 P1.0/CT0I (io), 11 P1.1/CT1I (io), 12 P1.2/CT2I (io), 13 P1.3/CT3I (io), 14 P1.4/T2 (io), 15 P1.5/RT2 (io), 16 P1.6/SCL (io), 17 P1.7/SDA (io), 18 P3.0/RxD (io), 19 P3.1/TxD (io), 20 P3.2/~{INT}0 (io), 21 NC, 22 NC, 23 P3.3/~{INT}1 (io), 24 PP3.4/T0 (io), 25 P3.5/T1 (io), 26 P3.6/~{WR} (io), 27 P3.7/~{RD} (io), 28 NC, 29 NC, 30 NC, 31 XTAL2 (out), 32 XTAL1 (in), 33 IC, 34 VSS (power), 35 VSS (power), 36 VSS (power), 37 NC, 38 P2.0/A08 (io), 39 P2.1/A09 (io), 40 P2.2/A10 (io), 41 P2.3/A11 (io), 42 P2.4/A12 (io), 43 NC, 44 NC, 45 P2.5/A13 (io), 46 P2.6/A14 (io), 47 P2.7/A15 (io), 48 ~{PSEN} (out), 49 ALE (out), 50 ~{EA} (in), 51 P0.7/AD7 (io), 52 P0.6/AD6 (io), 53 P0.5/AD5 (io), 54 P0.4/AD4 (io), 55 P0.3/AD3 (io), 56 P0.2/AD2 (io), 57 P0.1/AD1 (io), 58 P0.0/AD0 (io), 59 AVREF- (in), 60 AVREF+ (in), 61 AVSS (power), 62 NC, 63 AVDD (power), 64 P5.7/ADC7 (in), 65 P5.6/ADC6 (in), 66 P5.5/ADC5 (in), 67 P5.4/ADC4 (in), 68 P5.3/ADC3 (in), 69 P5.2/ADC2 (in), 70 P5.1/ADC1 (in), 71 P5.0/ADC0 (in), 72 VDD (power), 73 IC, 74 STADC (in), 75 ~{PWM}0 (out), 76 ~{PWM}1 (out), 77 ~{EW} (in), 78 NC, 79 NC, 80 P4.0/SMSR0 (io)

## P83C552EHA/xxx
designator U?
8k Mask Programmable ROM, Single-Chip 8-Bit Microcontroller with 10-bit A/D, Capture/Compare Timer, High-Speed Outputs, PWM
footprint SOT188-2_N (Leaded Chip Carrier, 68-Leads, Body 24.2x24.2mm, Pitch 1.27mm, IPC Medium Density)
footprint SOT188-2_L (Leaded Chip Carrier, 68-Leads, Body 24.2x24.2mm, Pitch 1.27mm, IPC High Density)
footprint SOT188-2_M (Leaded Chip Carrier, 68-Leads, Body 24.2x24.2mm, Pitch 1.27mm, IPC Low Density)
pins: 1 P5.0/ADC0 (in), 2 VDD (power), 3 STADC (in), 4 ~{PWM}0 (out), 5 ~{PWM}1 (out), 6 ~{EW} (in), 7 P4.0/CMSR0 (io), 8 P4.1/CMSR1 (io), 9 P4.2/CMSR2 (io), 10 P4.3/CMSR3 (io), 11 P4.4/CMSR4 (io), 12 P4.5/CMSR5 (io), 13 P4.6/CMT0 (io), 14 P4.7/CMT1 (io), 15 RST (io), 16 P1.0/CT0I (io), 17 P1.1/CT1I (io), 18 P1.2/CT2I (io), 19 P1.3/CT3I (io), 20 P1.4/T2 (io), 21 P1.5/RT2 (io), 22 P1.6/SCL (io), 23 P1.7/SDA (io), 24 P3.0/RxD (io), 25 P3.1/TxD (io), 26 P3.2/~{INT}0 (io), 27 P3.3/~{INT}1 (io), 28 P3.4/T0 (io), 29 P3.5/T1 (io), 30 P3.6/~{WR} (io), 31 P3.7/~{RD} (io), 32 NC, 33 NC, 34 XTAL2 (out), 35 XTAL1 (in), 36 VSS (power), 37 VSS (power), 38 NC, 39 P2.0/A08 (io), 40 P2.1/A09 (io), 41 P2.2/A10 (io), 42 P2.3/A11 (io), 43 P2.4/A12 (io), 44 P2.5/A13 (io), 45 P2.6/A14 (io), 46 P2.7/A15 (io), 47 ~{PSEN} (out), 48 ALE (out), 49 ~{EA} (in), 50 P0.7/AD7 (io), 51 P0.6/AD6 (io), 52 P0.5/AD5 (io), 53 P0.4/AD4 (io), 54 P0.3/AD3 (io), 55 P0.2/AD2 (io), 56 P0.1/AD1 (io), 57 P0.0/AD0 (io), 58 AVREF– (in), 59 AVREF+ (in), 60 AVSS (power), 61 AVDD (power), 62 P5.7/ADC7 (in), 63 P5.6/ADC6 (in), 64 P5.5/ADC5 (in), 65 P5.4/ADC4 (in), 66 P5.3/ADC3 (in), 67 P5.2/ADC2 (in), 68 P5.1/ADC1 (in)

## P83C552EHB/xxx
designator U?
8k Mask Programmable ROM, Single-Chip 8-Bit Microcontroller with 10-bit A/D, Capture/Compare Timer, High-Speed Outputs, PWM; DoNotConnect: Pins 33 & 73 are internally connected (IC), do not use.
footprint SOT318-2_N (QFP, 80-Leads, Body 20x14mm, Pitch 0.8mm, IPC Medium Density)
footprint SOT318-2_L (QFP, 80-Leads, Body 20x14mm, Pitch 0.8mm, IPC High Density)
footprint SOT318-2_M (QFP, 80-Leads, Body 20x14mm, Pitch 0.8mm, IPC Low Density)
pins: 1 P4.1/CMSR1 (io), 2 P4.2/CMSR2 (io), 3 NC, 4 P4.3/CMSR3 (io), 5 P4.4/CMSR4 (io), 6 P4.5/CMSR5 (io), 7 P4.6/CMT0 (io), 8 P4.7/CMT1 (io), 9 RST (io), 10 P1.0/CT0I (io), 11 P1.1/CT1I (io), 12 P1.2/CT2I (io), 13 P1.3/CT3I (io), 14 P1.4/T2 (io), 15 P1.5/RT2 (io), 16 P1.6/SCL (io), 17 P1.7/SDA (io), 18 P3.0/RxD (io), 19 P3.1/TxD (io), 20 P3.2/~{INT}0 (io), 21 NC, 22 NC, 23 P3.3/~{INT}1 (io), 24 PP3.4/T0 (io), 25 P3.5/T1 (io), 26 P3.6/~{WR} (io), 27 P3.7/~{RD} (io), 28 NC, 29 NC, 30 NC, 31 XTAL2 (out), 32 XTAL1 (in), 33 IC, 34 VSS (power), 35 VSS (power), 36 VSS (power), 37 NC, 38 P2.0/A08 (io), 39 P2.1/A09 (io), 40 P2.2/A10 (io), 41 P2.3/A11 (io), 42 P2.4/A12 (io), 43 NC, 44 NC, 45 P2.5/A13 (io), 46 P2.6/A14 (io), 47 P2.7/A15 (io), 48 ~{PSEN} (out), 49 ALE (out), 50 ~{EA} (in), 51 P0.7/AD7 (io), 52 P0.6/AD6 (io), 53 P0.5/AD5 (io), 54 P0.4/AD4 (io), 55 P0.3/AD3 (io), 56 P0.2/AD2 (io), 57 P0.1/AD1 (io), 58 P0.0/AD0 (io), 59 AVREF- (in), 60 AVREF+ (in), 61 AVSS (power), 62 NC, 63 AVDD (power), 64 P5.7/ADC7 (in), 65 P5.6/ADC6 (in), 66 P5.5/ADC5 (in), 67 P5.4/ADC4 (in), 68 P5.3/ADC3 (in), 69 P5.2/ADC2 (in), 70 P5.1/ADC1 (in), 71 P5.0/ADC0 (in), 72 VDD (power), 73 IC, 74 STADC (in), 75 ~{PWM}0 (out), 76 ~{PWM}1 (out), 77 ~{EW} (in), 78 NC, 79 NC, 80 P4.0/SMSR0 (io)

## P83C552IBA/xxx
designator U?
8k Mask Programmable ROM, Single-Chip 8-Bit Microcontroller with 10-bit A/D, Capture/Compare Timer, High-Speed Outputs, PWM
footprint SOT188-2_N (Leaded Chip Carrier, 68-Leads, Body 24.2x24.2mm, Pitch 1.27mm, IPC Medium Density)
footprint SOT188-2_L (Leaded Chip Carrier, 68-Leads, Body 24.2x24.2mm, Pitch 1.27mm, IPC High Density)
footprint SOT188-2_M (Leaded Chip Carrier, 68-Leads, Body 24.2x24.2mm, Pitch 1.27mm, IPC Low Density)
pins: 1 P5.0/ADC0 (in), 2 VDD (power), 3 STADC (in), 4 ~{PWM}0 (out), 5 ~{PWM}1 (out), 6 ~{EW} (in), 7 P4.0/CMSR0 (io), 8 P4.1/CMSR1 (io), 9 P4.2/CMSR2 (io), 10 P4.3/CMSR3 (io), 11 P4.4/CMSR4 (io), 12 P4.5/CMSR5 (io), 13 P4.6/CMT0 (io), 14 P4.7/CMT1 (io), 15 RST (io), 16 P1.0/CT0I (io), 17 P1.1/CT1I (io), 18 P1.2/CT2I (io), 19 P1.3/CT3I (io), 20 P1.4/T2 (io), 21 P1.5/RT2 (io), 22 P1.6/SCL (io), 23 P1.7/SDA (io), 24 P3.0/RxD (io), 25 P3.1/TxD (io), 26 P3.2/~{INT}0 (io), 27 P3.3/~{INT}1 (io), 28 P3.4/T0 (io), 29 P3.5/T1 (io), 30 P3.6/~{WR} (io), 31 P3.7/~{RD} (io), 32 NC, 33 NC, 34 XTAL2 (out), 35 XTAL1 (in), 36 VSS (power), 37 VSS (power), 38 NC, 39 P2.0/A08 (io), 40 P2.1/A09 (io), 41 P2.2/A10 (io), 42 P2.3/A11 (io), 43 P2.4/A12 (io), 44 P2.5/A13 (io), 45 P2.6/A14 (io), 46 P2.7/A15 (io), 47 ~{PSEN} (out), 48 ALE (out), 49 ~{EA} (in), 50 P0.7/AD7 (io), 51 P0.6/AD6 (io), 52 P0.5/AD5 (io), 53 P0.4/AD4 (io), 54 P0.3/AD3 (io), 55 P0.2/AD2 (io), 56 P0.1/AD1 (io), 57 P0.0/AD0 (io), 58 AVREF– (in), 59 AVREF+ (in), 60 AVSS (power), 61 AVDD (power), 62 P5.7/ADC7 (in), 63 P5.6/ADC6 (in), 64 P5.5/ADC5 (in), 65 P5.4/ADC4 (in), 66 P5.3/ADC3 (in), 67 P5.2/ADC2 (in), 68 P5.1/ADC1 (in)

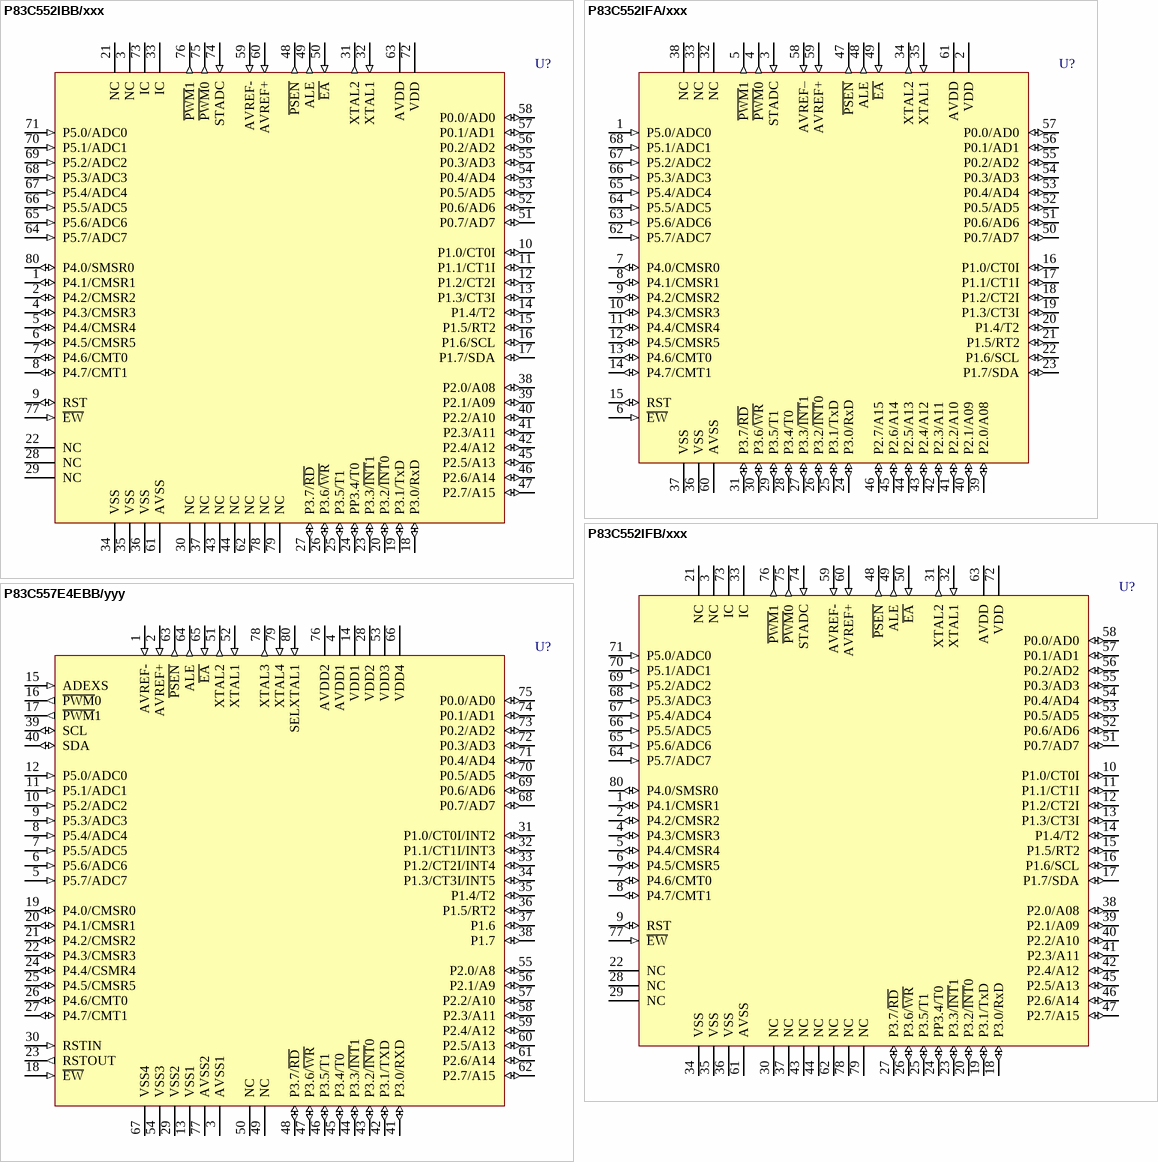
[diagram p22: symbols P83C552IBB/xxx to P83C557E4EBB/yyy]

## P83C552IBB/xxx
designator U?
8k Mask Programmable ROM, Single-Chip 8-Bit Microcontroller with 10-bit A/D, Capture/Compare Timer, High-Speed Outputs, PWM; DoNotConnect: Pins 33 & 73 are internally connected (IC), do not use.
footprint SOT318-2_N (QFP, 80-Leads, Body 20x14mm, Pitch 0.8mm, IPC Medium Density)
footprint SOT318-2_L (QFP, 80-Leads, Body 20x14mm, Pitch 0.8mm, IPC High Density)
footprint SOT318-2_M (QFP, 80-Leads, Body 20x14mm, Pitch 0.8mm, IPC Low Density)
pins: 1 P4.1/CMSR1 (io), 2 P4.2/CMSR2 (io), 3 NC, 4 P4.3/CMSR3 (io), 5 P4.4/CMSR4 (io), 6 P4.5/CMSR5 (io), 7 P4.6/CMT0 (io), 8 P4.7/CMT1 (io), 9 RST (io), 10 P1.0/CT0I (io), 11 P1.1/CT1I (io), 12 P1.2/CT2I (io), 13 P1.3/CT3I (io), 14 P1.4/T2 (io), 15 P1.5/RT2 (io), 16 P1.6/SCL (io), 17 P1.7/SDA (io), 18 P3.0/RxD (io), 19 P3.1/TxD (io), 20 P3.2/~{INT}0 (io), 21 NC, 22 NC, 23 P3.3/~{INT}1 (io), 24 PP3.4/T0 (io), 25 P3.5/T1 (io), 26 P3.6/~{WR} (io), 27 P3.7/~{RD} (io), 28 NC, 29 NC, 30 NC, 31 XTAL2 (out), 32 XTAL1 (in), 33 IC, 34 VSS (power), 35 VSS (power), 36 VSS (power), 37 NC, 38 P2.0/A08 (io), 39 P2.1/A09 (io), 40 P2.2/A10 (io), 41 P2.3/A11 (io), 42 P2.4/A12 (io), 43 NC, 44 NC, 45 P2.5/A13 (io), 46 P2.6/A14 (io), 47 P2.7/A15 (io), 48 ~{PSEN} (out), 49 ALE (out), 50 ~{EA} (in), 51 P0.7/AD7 (io), 52 P0.6/AD6 (io), 53 P0.5/AD5 (io), 54 P0.4/AD4 (io), 55 P0.3/AD3 (io), 56 P0.2/AD2 (io), 57 P0.1/AD1 (io), 58 P0.0/AD0 (io), 59 AVREF- (in), 60 AVREF+ (in), 61 AVSS (power), 62 NC, 63 AVDD (power), 64 P5.7/ADC7 (in), 65 P5.6/ADC6 (in), 66 P5.5/ADC5 (in), 67 P5.4/ADC4 (in), 68 P5.3/ADC3 (in), 69 P5.2/ADC2 (in), 70 P5.1/ADC1 (in), 71 P5.0/ADC0 (in), 72 VDD (power), 73 IC, 74 STADC (in), 75 ~{PWM}0 (out), 76 ~{PWM}1 (out), 77 ~{EW} (in), 78 NC, 79 NC, 80 P4.0/SMSR0 (io)

## P83C552IFA/xxx
designator U?
8k Mask Programmable ROM, Single-Chip 8-Bit Microcontroller with 10-bit A/D, Capture/Compare Timer, High-Speed Outputs, PWM
footprint SOT188-2_N (Leaded Chip Carrier, 68-Leads, Body 24.2x24.2mm, Pitch 1.27mm, IPC Medium Density)
footprint SOT188-2_L (Leaded Chip Carrier, 68-Leads, Body 24.2x24.2mm, Pitch 1.27mm, IPC High Density)
footprint SOT188-2_M (Leaded Chip Carrier, 68-Leads, Body 24.2x24.2mm, Pitch 1.27mm, IPC Low Density)
pins: 1 P5.0/ADC0 (in), 2 VDD (power), 3 STADC (in), 4 ~{PWM}0 (out), 5 ~{PWM}1 (out), 6 ~{EW} (in), 7 P4.0/CMSR0 (io), 8 P4.1/CMSR1 (io), 9 P4.2/CMSR2 (io), 10 P4.3/CMSR3 (io), 11 P4.4/CMSR4 (io), 12 P4.5/CMSR5 (io), 13 P4.6/CMT0 (io), 14 P4.7/CMT1 (io), 15 RST (io), 16 P1.0/CT0I (io), 17 P1.1/CT1I (io), 18 P1.2/CT2I (io), 19 P1.3/CT3I (io), 20 P1.4/T2 (io), 21 P1.5/RT2 (io), 22 P1.6/SCL (io), 23 P1.7/SDA (io), 24 P3.0/RxD (io), 25 P3.1/TxD (io), 26 P3.2/~{INT}0 (io), 27 P3.3/~{INT}1 (io), 28 P3.4/T0 (io), 29 P3.5/T1 (io), 30 P3.6/~{WR} (io), 31 P3.7/~{RD} (io), 32 NC, 33 NC, 34 XTAL2 (out), 35 XTAL1 (in), 36 VSS (power), 37 VSS (power), 38 NC, 39 P2.0/A08 (io), 40 P2.1/A09 (io), 41 P2.2/A10 (io), 42 P2.3/A11 (io), 43 P2.4/A12 (io), 44 P2.5/A13 (io), 45 P2.6/A14 (io), 46 P2.7/A15 (io), 47 ~{PSEN} (out), 48 ALE (out), 49 ~{EA} (in), 50 P0.7/AD7 (io), 51 P0.6/AD6 (io), 52 P0.5/AD5 (io), 53 P0.4/AD4 (io), 54 P0.3/AD3 (io), 55 P0.2/AD2 (io), 56 P0.1/AD1 (io), 57 P0.0/AD0 (io), 58 AVREF– (in), 59 AVREF+ (in), 60 AVSS (power), 61 AVDD (power), 62 P5.7/ADC7 (in), 63 P5.6/ADC6 (in), 64 P5.5/ADC5 (in), 65 P5.4/ADC4 (in), 66 P5.3/ADC3 (in), 67 P5.2/ADC2 (in), 68 P5.1/ADC1 (in)

## P83C552IFB/xxx
designator U?
8k Mask Programmable ROM, Single-Chip 8-Bit Microcontroller with 10-bit A/D, Capture/Compare Timer, High-Speed Outputs, PWM; DoNotConnect: Pins 33 & 73 are internally connected (IC), do not use.
footprint SOT318-2_N (QFP, 80-Leads, Body 20x14mm, Pitch 0.8mm, IPC Medium Density)
footprint SOT318-2_L (QFP, 80-Leads, Body 20x14mm, Pitch 0.8mm, IPC High Density)
footprint SOT318-2_M (QFP, 80-Leads, Body 20x14mm, Pitch 0.8mm, IPC Low Density)
pins: 1 P4.1/CMSR1 (io), 2 P4.2/CMSR2 (io), 3 NC, 4 P4.3/CMSR3 (io), 5 P4.4/CMSR4 (io), 6 P4.5/CMSR5 (io), 7 P4.6/CMT0 (io), 8 P4.7/CMT1 (io), 9 RST (io), 10 P1.0/CT0I (io), 11 P1.1/CT1I (io), 12 P1.2/CT2I (io), 13 P1.3/CT3I (io), 14 P1.4/T2 (io), 15 P1.5/RT2 (io), 16 P1.6/SCL (io), 17 P1.7/SDA (io), 18 P3.0/RxD (io), 19 P3.1/TxD (io), 20 P3.2/~{INT}0 (io), 21 NC, 22 NC, 23 P3.3/~{INT}1 (io), 24 PP3.4/T0 (io), 25 P3.5/T1 (io), 26 P3.6/~{WR} (io), 27 P3.7/~{RD} (io), 28 NC, 29 NC, 30 NC, 31 XTAL2 (out), 32 XTAL1 (in), 33 IC, 34 VSS (power), 35 VSS (power), 36 VSS (power), 37 NC, 38 P2.0/A08 (io), 39 P2.1/A09 (io), 40 P2.2/A10 (io), 41 P2.3/A11 (io), 42 P2.4/A12 (io), 43 NC, 44 NC, 45 P2.5/A13 (io), 46 P2.6/A14 (io), 47 P2.7/A15 (io), 48 ~{PSEN} (out), 49 ALE (out), 50 ~{EA} (in), 51 P0.7/AD7 (io), 52 P0.6/AD6 (io), 53 P0.5/AD5 (io), 54 P0.4/AD4 (io), 55 P0.3/AD3 (io), 56 P0.2/AD2 (io), 57 P0.1/AD1 (io), 58 P0.0/AD0 (io), 59 AVREF- (in), 60 AVREF+ (in), 61 AVSS (power), 62 NC, 63 AVDD (power), 64 P5.7/ADC7 (in), 65 P5.6/ADC6 (in), 66 P5.5/ADC5 (in), 67 P5.4/ADC4 (in), 68 P5.3/ADC3 (in), 69 P5.2/ADC2 (in), 70 P5.1/ADC1 (in), 71 P5.0/ADC0 (in), 72 VDD (power), 73 IC, 74 STADC (in), 75 ~{PWM}0 (out), 76 ~{PWM}1 (out), 77 ~{EW} (in), 78 NC, 79 NC, 80 P4.0/SMSR0 (io)

## P83C557E4EBB/yyy
designator U?
Single-Chip 8-Bit Microcontroller, ROM coded Type
footprint SOT318-1_N (QFP, 80-Leads, Body 20x14mm, Pitch 0.8mm, IPC Medium Density)
footprint SOT318-1_L (QFP, 80-Leads, Body 20x14mm, Pitch 0.8mm, IPC High Density)
footprint SOT318-1_M (QFP, 80-Leads, Body 20x14mm, Pitch 0.8mm, IPC Low Density)
pins: 1 AVREF- (in), 2 AVREF+ (in), 3 AVSS1 (power), 4 AVDD1 (power), 5 P5.7/ADC7 (in), 6 P5.6/ADC6 (in), 7 P5.5/ADC5 (in), 8 P5.4/ADC4 (in), 9 P5.3/ADC3 (in), 10 P5.2/ADC2 (in), 11 P5.1/ADC1 (in), 12 P5.0/ADC0 (in), 13 VSS1 (power), 14 VDD1 (power), 15 ADEXS (in), 16 ~{PWM}0 (out), 17 ~{PWM}1 (out), 18 ~{EW} (in), 19 P4.0/CMSR0 (io), 20 P4.1/CMSR1 (io), 21 P4.2/CMSR2 (io), 22 P4.3/CMSR3 (io), 23 RSTOUT (out), 24 P4.4/CSMR4 (io), 25 P4.5/CMSR5 (io), 26 P4.6/CMT0 (io), 27 P4.7/CMT1 (io), 28 VDD2 (power), 29 VSS2 (power), 30 RSTIN (in), 31 P1.0/CT0I/INT2 (io), 32 P1.1/CT1I/INT3 (io), 33 P1.2/CT2I/INT4 (io), 34 P1.3/CT3I/INT5 (io), 35 P1.4/T2 (io), 36 P1.5/RT2 (io), 37 P1.6 (io), 38 P1.7 (io), 39 SCL (io), 40 SDA (io), 41 P3.0/RXD (io), 42 P3.1/TXD (io), 43 P3.2/~{INT}0 (io), 44 P3.3/~{INT}1 (io), 45 P3.4/T0 (io), 46 P3.5/T1 (io), 47 P3.6/~{WR} (io), 48 P3.7/~{RD} (io), 49 NC, 50 NC, 51 XTAL2 (out), 52 XTAL1 (in), 53 VDD3 (power), 54 VSS3 (power), 55 P2.0/A8 (io), 56 P2.1/A9 (io), 57 P2.2/A10 (io), 58 P2.3/A11 (io), 59 P2.4/A12 (io), 60 P2.5/A13 (io), 61 P2.6/A14 (io), 62 P2.7/A15 (io), 63 ~{PSEN} (out), 64 ALE (out), 65 ~{EA} (in), 66 VDD4 (power), 67 VSS4 (power), 68 P0.7/AD7 (io), 69 P0.6/AD6 (io), 70 P0.5/AD5 (io), 71 P0.4/AD4 (io), 72 P0.3/AD3 (io), 73 P0.2/AD2 (io), 74 P0.1/AD1 (io), 75 P0.0/AD0 (io), 76 AVDD2 (power), 77 AVSS2 (power), 78 XTAL3 (out), 79 XTAL4 (in), 80 SELXTAL1 (in)

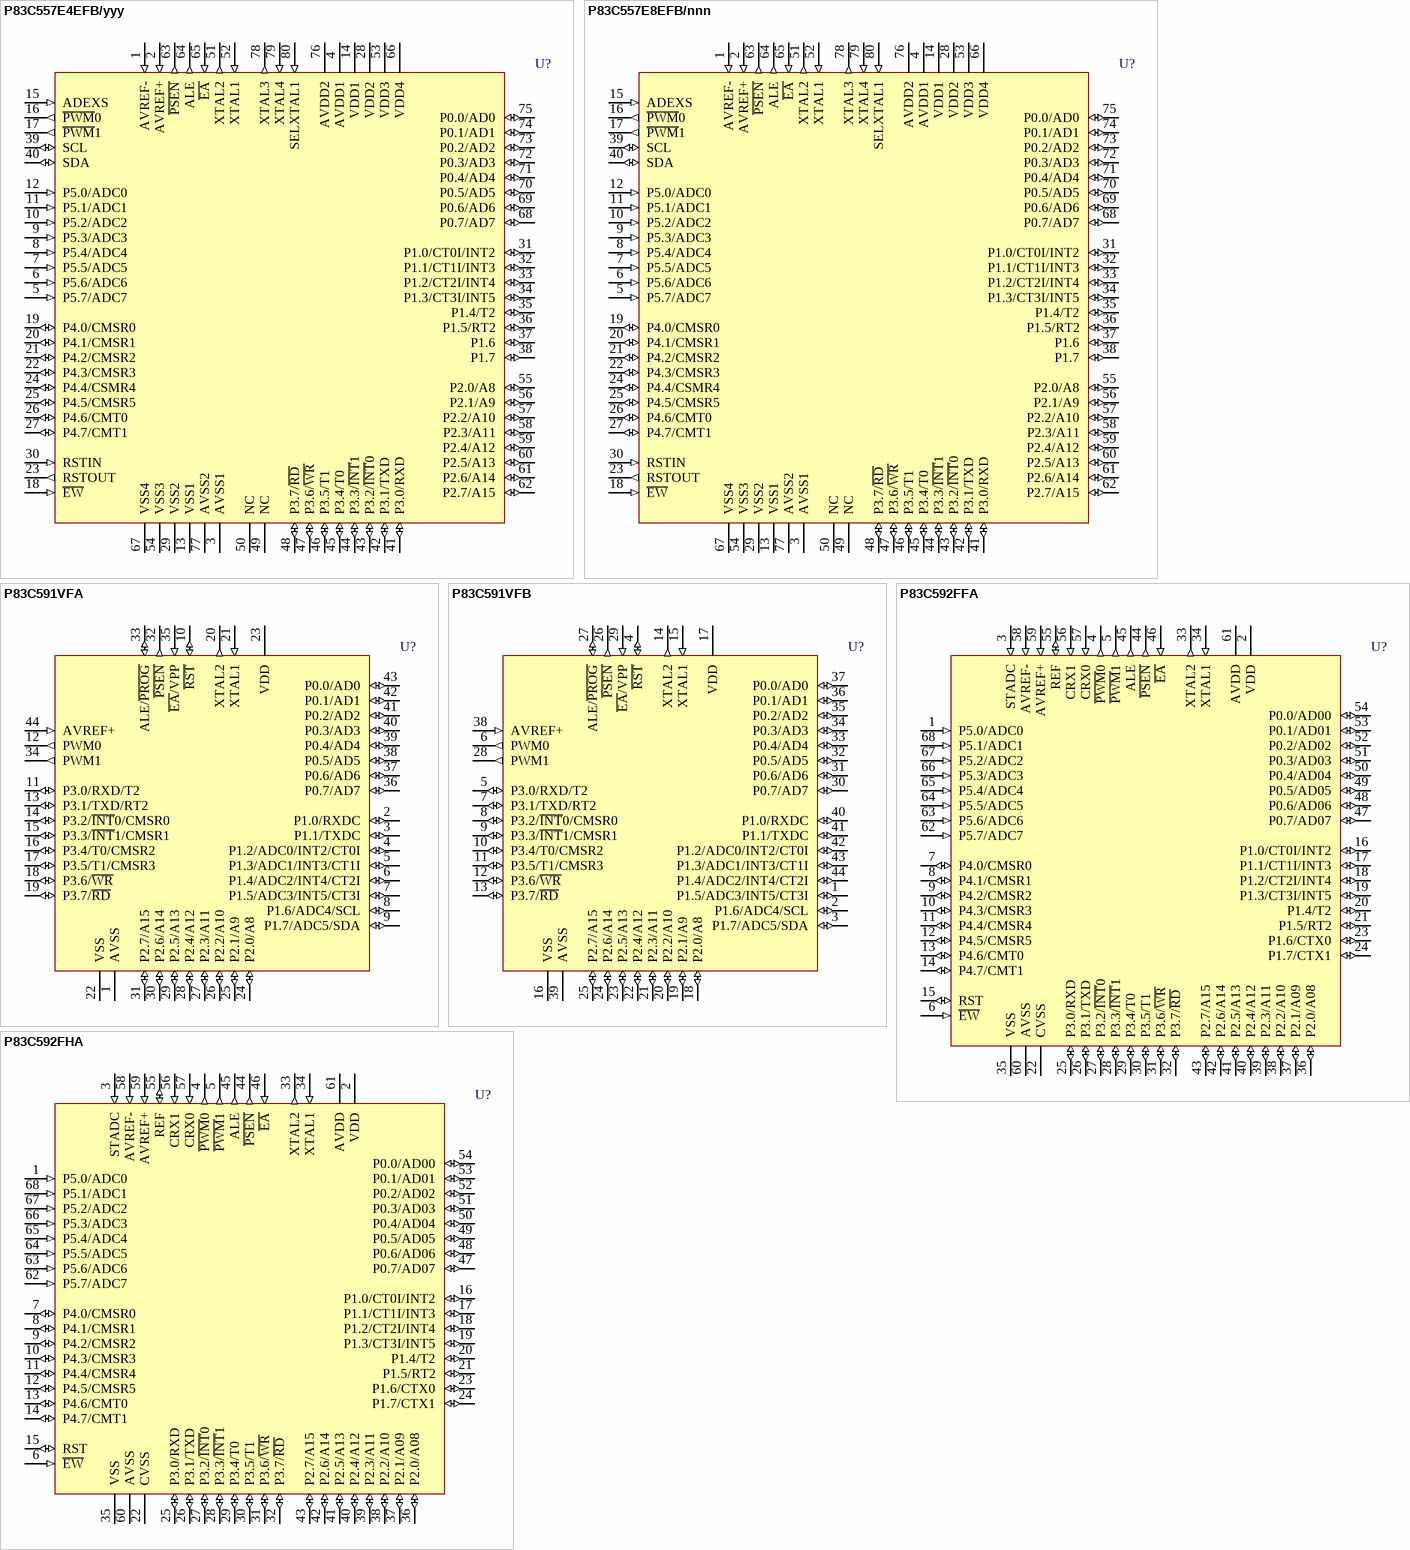
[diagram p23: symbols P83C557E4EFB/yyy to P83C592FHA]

## P83C557E4EFB/yyy
designator U?
Single-Chip 8-Bit Microcontroller, ROM coded Type
footprint SOT318-1_N (QFP, 80-Leads, Body 20x14mm, Pitch 0.8mm, IPC Medium Density)
footprint SOT318-1_L (QFP, 80-Leads, Body 20x14mm, Pitch 0.8mm, IPC High Density)
footprint SOT318-1_M (QFP, 80-Leads, Body 20x14mm, Pitch 0.8mm, IPC Low Density)
pins: 1 AVREF- (in), 2 AVREF+ (in), 3 AVSS1 (power), 4 AVDD1 (power), 5 P5.7/ADC7 (in), 6 P5.6/ADC6 (in), 7 P5.5/ADC5 (in), 8 P5.4/ADC4 (in), 9 P5.3/ADC3 (in), 10 P5.2/ADC2 (in), 11 P5.1/ADC1 (in), 12 P5.0/ADC0 (in), 13 VSS1 (power), 14 VDD1 (power), 15 ADEXS (in), 16 ~{PWM}0 (out), 17 ~{PWM}1 (out), 18 ~{EW} (in), 19 P4.0/CMSR0 (io), 20 P4.1/CMSR1 (io), 21 P4.2/CMSR2 (io), 22 P4.3/CMSR3 (io), 23 RSTOUT (out), 24 P4.4/CSMR4 (io), 25 P4.5/CMSR5 (io), 26 P4.6/CMT0 (io), 27 P4.7/CMT1 (io), 28 VDD2 (power), 29 VSS2 (power), 30 RSTIN (in), 31 P1.0/CT0I/INT2 (io), 32 P1.1/CT1I/INT3 (io), 33 P1.2/CT2I/INT4 (io), 34 P1.3/CT3I/INT5 (io), 35 P1.4/T2 (io), 36 P1.5/RT2 (io), 37 P1.6 (io), 38 P1.7 (io), 39 SCL (io), 40 SDA (io), 41 P3.0/RXD (io), 42 P3.1/TXD (io), 43 P3.2/~{INT}0 (io), 44 P3.3/~{INT}1 (io), 45 P3.4/T0 (io), 46 P3.5/T1 (io), 47 P3.6/~{WR} (io), 48 P3.7/~{RD} (io), 49 NC, 50 NC, 51 XTAL2 (out), 52 XTAL1 (in), 53 VDD3 (power), 54 VSS3 (power), 55 P2.0/A8 (io), 56 P2.1/A9 (io), 57 P2.2/A10 (io), 58 P2.3/A11 (io), 59 P2.4/A12 (io), 60 P2.5/A13 (io), 61 P2.6/A14 (io), 62 P2.7/A15 (io), 63 ~{PSEN} (out), 64 ALE (out), 65 ~{EA} (in), 66 VDD4 (power), 67 VSS4 (power), 68 P0.7/AD7 (io), 69 P0.6/AD6 (io), 70 P0.5/AD5 (io), 71 P0.4/AD4 (io), 72 P0.3/AD3 (io), 73 P0.2/AD2 (io), 74 P0.1/AD1 (io), 75 P0.0/AD0 (io), 76 AVDD2 (power), 77 AVSS2 (power), 78 XTAL3 (out), 79 XTAL4 (in), 80 SELXTAL1 (in)

## P83C557E8EFB/nnn
designator U?
8-Bit Microcontroller, ROM coded Type
footprint SOT318-2_N (QFP, 80-Leads, Body 20x14mm, Pitch 0.8mm, IPC Medium Density)
footprint SOT318-2_L (QFP, 80-Leads, Body 20x14mm, Pitch 0.8mm, IPC High Density)
footprint SOT318-2_M (QFP, 80-Leads, Body 20x14mm, Pitch 0.8mm, IPC Low Density)
pins: 1 AVREF- (in), 2 AVREF+ (in), 3 AVSS1 (power), 4 AVDD1 (power), 5 P5.7/ADC7 (in), 6 P5.6/ADC6 (in), 7 P5.5/ADC5 (in), 8 P5.4/ADC4 (in), 9 P5.3/ADC3 (in), 10 P5.2/ADC2 (in), 11 P5.1/ADC1 (in), 12 P5.0/ADC0 (in), 13 VSS1 (power), 14 VDD1 (power), 15 ADEXS (in), 16 ~{PWM}0 (out), 17 ~{PWM}1 (out), 18 ~{EW} (in), 19 P4.0/CMSR0 (io), 20 P4.1/CMSR1 (io), 21 P4.2/CMSR2 (io), 22 P4.3/CMSR3 (io), 23 RSTOUT (out), 24 P4.4/CSMR4 (io), 25 P4.5/CMSR5 (io), 26 P4.6/CMT0 (io), 27 P4.7/CMT1 (io), 28 VDD2 (power), 29 VSS2 (power), 30 RSTIN (in), 31 P1.0/CT0I/INT2 (io), 32 P1.1/CT1I/INT3 (io), 33 P1.2/CT2I/INT4 (io), 34 P1.3/CT3I/INT5 (io), 35 P1.4/T2 (io), 36 P1.5/RT2 (io), 37 P1.6 (io), 38 P1.7 (io), 39 SCL (io), 40 SDA (io), 41 P3.0/RXD (io), 42 P3.1/TXD (io), 43 P3.2/~{INT}0 (io), 44 P3.3/~{INT}1 (io), 45 P3.4/T0 (io), 46 P3.5/T1 (io), 47 P3.6/~{WR} (io), 48 P3.7/~{RD} (io), 49 NC, 50 NC, 51 XTAL2 (out), 52 XTAL1 (in), 53 VDD3 (power), 54 VSS3 (power), 55 P2.0/A8 (io), 56 P2.1/A9 (io), 57 P2.2/A10 (io), 58 P2.3/A11 (io), 59 P2.4/A12 (io), 60 P2.5/A13 (io), 61 P2.6/A14 (io), 62 P2.7/A15 (io), 63 ~{PSEN} (out), 64 ALE (out), 65 ~{EA} (in), 66 VDD4 (power), 67 VSS4 (power), 68 P0.7/AD7 (io), 69 P0.6/AD6 (io), 70 P0.5/AD5 (io), 71 P0.4/AD4 (io), 72 P0.3/AD3 (io), 73 P0.2/AD2 (io), 74 P0.1/AD1 (io), 75 P0.0/AD0 (io), 76 AVDD2 (power), 77 AVSS2 (power), 78 XTAL3 (out), 79 XTAL4 (in), 80 SELXTAL1 (in)

## P83C591VFA
designator U?
Single-Chip 8-Bit Microcontroller with CAN Controller
footprint SOT187-2_N (Leaded Chip Carrier, 44-Leads, Body 16.6x16.6mm, Pitch 1.27mm, IPC Medium Density)
footprint SOT187-2_L (Leaded Chip Carrier, 44-Leads, Body 16.6x16.6mm, Pitch 1.27mm, IPC High Density)
footprint SOT187-2_M (Leaded Chip Carrier, 44-Leads, Body 16.6x16.6mm, Pitch 1.27mm, IPC Low Density)
pins: 1 AVSS (power), 2 P1.0/RXDC (io), 3 P1.1/TXDC (io), 4 P1.2/ADC0/INT2/CT0I (io), 5 P1.3/ADC1/INT3/CT1I (io), 6 P1.4/ADC2/INT4/CT2I (io), 7 P1.5/ADC3/INT5/CT3I (io), 8 P1.6/ADC4/SCL (io), 9 P1.7/ADC5/SDA (io), 10 ~{RST} (io), 11 P3.0/RXD/T2 (io), 12 PWM0 (out), 13 P3.1/TXD/RT2 (io), 14 P3.2/~{INT}0/CMSR0 (io), 15 P3.3/~{INT}1/CMSR1 (io), 16 P3.4/T0/CMSR2 (io), 17 P3.5/T1/CMSR3 (io), 18 P3.6/~{WR} (io), 19 P3.7/~{RD} (io), 20 XTAL2 (out), 21 XTAL1 (in), 22 VSS (power), 23 VDD (power), 24 P2.0/A8 (io), 25 P2.1/A9 (io), 26 P2.2/A10 (io), 27 P2.3/A11 (io), 28 P2.4/A12 (io), 29 P2.5/A13 (io), 30 P2.6/A14 (io), 31 P2.7/A15 (io), 32 ~{PSEN} (out), 33 ALE/~{PROG} (io), 34 PWM1 (out), 35 ~{EA}/VPP (in), 36 P0.7/AD7 (io), 37 P0.6/AD6 (io), 38 P0.5/AD5 (io), 39 P0.4/AD4 (io), 40 P0.3/AD3 (io), 41 P0.2/AD2 (io), 42 P0.1/AD1 (io), 43 P0.0/AD0 (io), 44 AVREF+ (in)

## P83C591VFB
designator U?
Single-Chip 8-Bit Microcontroller with CAN Controller
footprint SOT307-2_N (QFP, 44-Leads, Body 10x10mm, Pitch 0.8mm, IPC Medium Density)
footprint SOT307-2_L (QFP, 44-Leads, Body 10x10mm, Pitch 0.8mm, IPC High Density)
footprint SOT307-2_M (QFP, 44-Leads, Body 10x10mm, Pitch 0.8mm, IPC Low Density)
pins: 1 P1.5/ADC3/INT5/CT3I (io), 2 P1.6/ADC4/SCL (io), 3 P1.7/ADC5/SDA (io), 4 ~{RST} (io), 5 P3.0/RXD/T2 (io), 6 PWM0 (out), 7 P3.1/TXD/RT2 (io), 8 P3.2/~{INT}0/CMSR0 (io), 9 P3.3/~{INT}1/CMSR1 (io), 10 P3.4/T0/CMSR2 (io), 11 P3.5/T1/CMSR3 (io), 12 P3.6/~{WR} (io), 13 P3.7/~{RD} (io), 14 XTAL2 (out), 15 XTAL1 (in), 16 VSS (power), 17 VDD (power), 18 P2.0/A8 (io), 19 P2.1/A9 (io), 20 P2.2/A10 (io), 21 P2.3/A11 (io), 22 P2.4/A12 (io), 23 P2.5/A13 (io), 24 P2.6/A14 (io), 25 P2.7/A15 (io), 26 ~{PSEN} (out), 27 ALE/~{PROG} (io), 28 PWM1 (out), 29 ~{EA}/VPP (in), 30 P0.7/AD7 (io), 31 P0.6/AD6 (io), 32 P0.5/AD5 (io), 33 P0.4/AD4 (io), 34 P0.3/AD3 (io), 35 P0.2/AD2 (io), 36 P0.1/AD1 (io), 37 P0.0/AD0 (io), 38 AVREF+ (in), 39 AVSS (power), 40 P1.0/RXDC (io), 41 P1.1/TXDC (io), 42 P1.2/ADC0/INT2/CT0I (io), 43 P1.3/ADC1/INT3/CT1I (io), 44 P1.4/ADC2/INT4/CT2I (io)

## P83C592FFA
designator U?
8-Bit Microcontroller with On-Chip CAN, with ROM
footprint SOT188-2_N (Leaded Chip Carrier, 68-Leads, Body 24.2x24.2mm, Pitch 1.27mm, IPC Medium Density)
footprint SOT188-2_L (Leaded Chip Carrier, 68-Leads, Body 24.2x24.2mm, Pitch 1.27mm, IPC High Density)
footprint SOT188-2_M (Leaded Chip Carrier, 68-Leads, Body 24.2x24.2mm, Pitch 1.27mm, IPC Low Density)
pins: 1 P5.0/ADC0 (in), 2 VDD (power), 3 STADC (in), 4 ~{PWM}0 (out), 5 ~{PWM}1 (out), 6 ~{EW} (in), 7 P4.0/CMSR0 (io), 8 P4.1/CMSR1 (io), 9 P4.2/CMSR2 (io), 10 P4.3/CMSR3 (io), 11 P4.4/CMSR4 (io), 12 P4.5/CMSR5 (io), 13 P4.6/CMT0 (io), 14 P4.7/CMT1 (io), 15 RST (io), 16 P1.0/CT0I/INT2 (io), 17 P1.1/CT1I/INT3 (io), 18 P1.2/CT2I/INT4 (io), 19 P1.3/CT3I/INT5 (io), 20 P1.4/T2 (io), 21 P1.5/RT2 (io), 22 CVSS (power), 23 P1.6/CTX0 (io), 24 P1.7/CTX1 (io), 25 P3.0/RXD (io), 26 P3.1/TXD (io), 27 P3.2/~{INT}0 (io), 28 P3.3/~{INT}1 (io), 29 P3.4/T0 (io), 30 P3.5/T1 (io), 31 P3.6/~{WR} (io), 32 P3.7/~{RD} (io), 33 XTAL2 (out), 34 XTAL1 (in), 35 VSS (power), 36 P2.0/A08 (io), 37 P2.1/A09 (io), 38 P2.2/A10 (io), 39 P2.3/A11 (io), 40 P2.4/A12 (io), 41 P2.5/A13 (io), 42 P2.6/A14 (io), 43 P2.7/A15 (io), 44 ~{PSEN} (out), 45 ALE (out), 46 ~{EA} (in), 47 P0.7/AD07 (io), 48 P0.6/AD06 (io), 49 P0.5/AD05 (io), 50 P0.4/AD04 (io), 51 P0.3/AD03 (io), 52 P0.2/AD02 (io), 53 P0.1/AD01 (io), 54 P0.0/AD00 (io), 55 REF (io), 56 CRX1 (in), 57 CRX0 (in), 58 AVREF- (in), 59 AVREF+ (in), 60 AVSS (power), 61 AVDD (power), 62 P5.7/ADC7 (in), 63 P5.6/ADC6 (in), 64 P5.5/ADC5 (in), 65 P5.4/ADC4 (in), 66 P5.3/ADC3 (in), 67 P5.2/ADC2 (in), 68 P5.1/ADC1 (in)

## P83C592FHA
designator U?
8-Bit Microcontroller with On-Chip CAN, with ROM
footprint SOT188-2_N (Leaded Chip Carrier, 68-Leads, Body 24.2x24.2mm, Pitch 1.27mm, IPC Medium Density)
footprint SOT188-2_L (Leaded Chip Carrier, 68-Leads, Body 24.2x24.2mm, Pitch 1.27mm, IPC High Density)
footprint SOT188-2_M (Leaded Chip Carrier, 68-Leads, Body 24.2x24.2mm, Pitch 1.27mm, IPC Low Density)
pins: 1 P5.0/ADC0 (in), 2 VDD (power), 3 STADC (in), 4 ~{PWM}0 (out), 5 ~{PWM}1 (out), 6 ~{EW} (in), 7 P4.0/CMSR0 (io), 8 P4.1/CMSR1 (io), 9 P4.2/CMSR2 (io), 10 P4.3/CMSR3 (io), 11 P4.4/CMSR4 (io), 12 P4.5/CMSR5 (io), 13 P4.6/CMT0 (io), 14 P4.7/CMT1 (io), 15 RST (io), 16 P1.0/CT0I/INT2 (io), 17 P1.1/CT1I/INT3 (io), 18 P1.2/CT2I/INT4 (io), 19 P1.3/CT3I/INT5 (io), 20 P1.4/T2 (io), 21 P1.5/RT2 (io), 22 CVSS (power), 23 P1.6/CTX0 (io), 24 P1.7/CTX1 (io), 25 P3.0/RXD (io), 26 P3.1/TXD (io), 27 P3.2/~{INT}0 (io), 28 P3.3/~{INT}1 (io), 29 P3.4/T0 (io), 30 P3.5/T1 (io), 31 P3.6/~{WR} (io), 32 P3.7/~{RD} (io), 33 XTAL2 (out), 34 XTAL1 (in), 35 VSS (power), 36 P2.0/A08 (io), 37 P2.1/A09 (io), 38 P2.2/A10 (io), 39 P2.3/A11 (io), 40 P2.4/A12 (io), 41 P2.5/A13 (io), 42 P2.6/A14 (io), 43 P2.7/A15 (io), 44 ~{PSEN} (out), 45 ALE (out), 46 ~{EA} (in), 47 P0.7/AD07 (io), 48 P0.6/AD06 (io), 49 P0.5/AD05 (io), 50 P0.4/AD04 (io), 51 P0.3/AD03 (io), 52 P0.2/AD02 (io), 53 P0.1/AD01 (io), 54 P0.0/AD00 (io), 55 REF (io), 56 CRX1 (in), 57 CRX0 (in), 58 AVREF- (in), 59 AVREF+ (in), 60 AVSS (power), 61 AVDD (power), 62 P5.7/ADC7 (in), 63 P5.6/ADC6 (in), 64 P5.5/ADC5 (in), 65 P5.4/ADC4 (in), 66 P5.3/ADC3 (in), 67 P5.2/ADC2 (in), 68 P5.1/ADC1 (in)

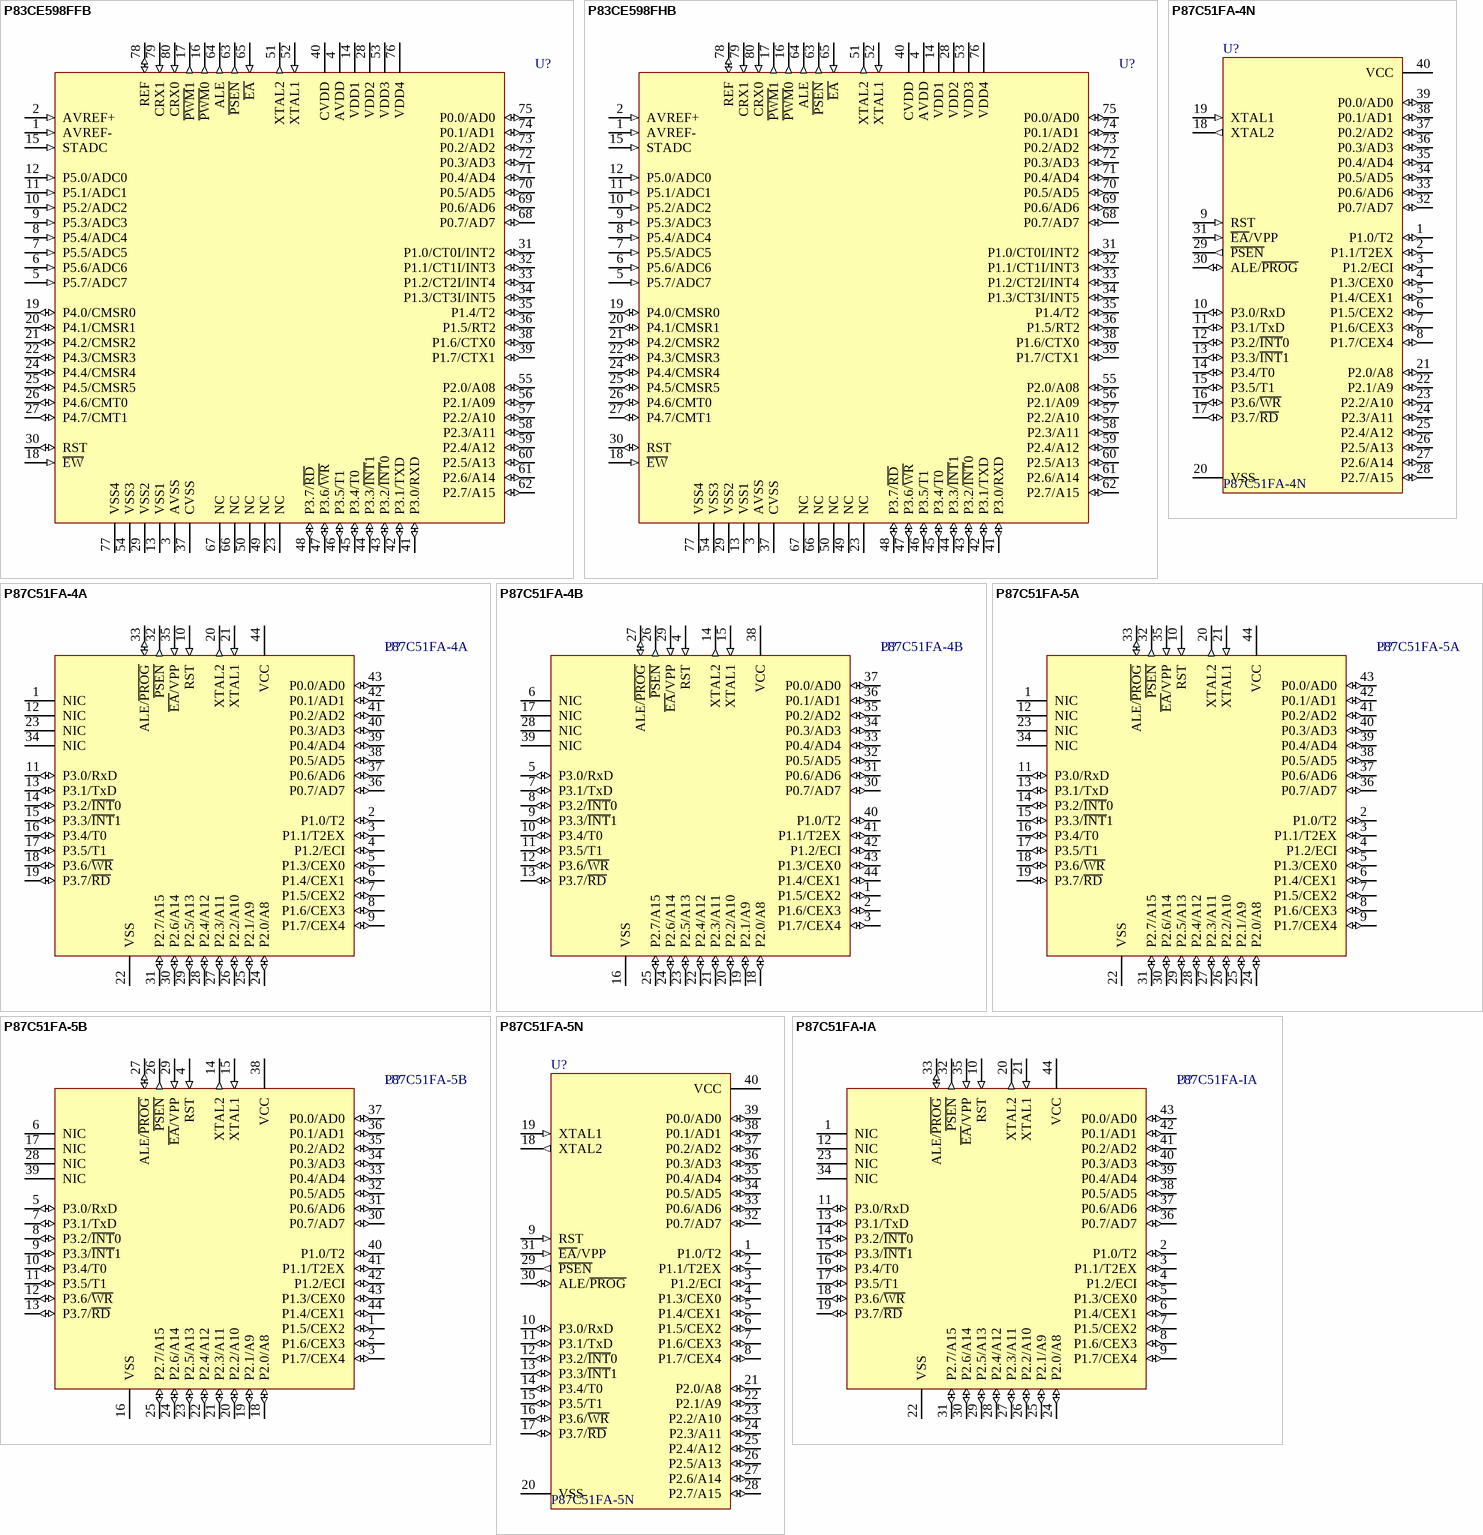
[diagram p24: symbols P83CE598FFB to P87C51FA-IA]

## P83CE598FFB
designator U?
8-Bit Microcontroller with On-Chip CAN, with ROM
footprint SOT318-1_N (QFP, 80-Leads, Body 20x14mm, Pitch 0.8mm, IPC Medium Density)
footprint SOT318-1_L (QFP, 80-Leads, Body 20x14mm, Pitch 0.8mm, IPC High Density)
footprint SOT318-1_M (QFP, 80-Leads, Body 20x14mm, Pitch 0.8mm, IPC Low Density)
pins: 1 AVREF- (in), 2 AVREF+ (in), 3 AVSS (power), 4 AVDD (power), 5 P5.7/ADC7 (in), 6 P5.6/ADC6 (in), 7 P5.5/ADC5 (in), 8 P5.4/ADC4 (in), 9 P5.3/ADC3 (in), 10 P5.2/ADC2 (in), 11 P5.1/ADC1 (in), 12 P5.0/ADC0 (in), 13 VSS1 (power), 14 VDD1 (power), 15 STADC (in), 16 ~{PWM}0 (out), 17 ~{PWM}1 (out), 18 ~{EW} (in), 19 P4.0/CMSR0 (io), 20 P4.1/CMSR1 (io), 21 P4.2/CMSR2 (io), 22 P4.3/CMSR3 (io), 23 NC, 24 P4.4/CMSR4 (io), 25 P4.5/CMSR5 (io), 26 P4.6/CMT0 (io), 27 P4.7/CMT1 (io), 28 VDD2 (power), 29 VSS2 (power), 30 RST (io), 31 P1.0/CT0I/INT2 (io), 32 P1.1/CT1I/INT3 (io), 33 P1.2/CT2I/INT4 (io), 34 P1.3/CT3I/INT5 (io), 35 P1.4/T2 (io), 36 P1.5/RT2 (io), 37 CVSS (power), 38 P1.6/CTX0 (io), 39 P1.7/CTX1 (io), 40 CVDD (power), 41 P3.0/RXD (io), 42 P3.1/TXD (io), 43 P3.2/~{INT}0 (io), 44 P3.3/~{INT}1 (io), 45 P3.4/T0 (io), 46 P3.5/T1 (io), 47 P3.6/~{WR} (io), 48 P3.7/~{RD} (io), 49 NC, 50 NC, 51 XTAL2 (out), 52 XTAL1 (in), 53 VDD3 (power), 54 VSS3 (power), 55 P2.0/A08 (io), 56 P2.1/A09 (io), 57 P2.2/A10 (io), 58 P2.3/A11 (io), 59 P2.4/A12 (io), 60 P2.5/A13 (io), 61 P2.6/A14 (io), 62 P2.7/A15 (io), 63 ~{PSEN} (out), 64 ALE (out), 65 ~{EA} (in), 66 NC, 67 NC, 68 P0.7/AD7 (io), 69 P0.6/AD6 (io), 70 P0.5/AD5 (io), 71 P0.4/AD4 (io), 72 P0.3/AD3 (io), 73 P0.2/AD2 (io), 74 P0.1/AD1 (io), 75 P0.0/AD0 (io), 76 VDD4 (power), 77 VSS4 (power), 78 REF (io), 79 CRX1 (in), 80 CRX0 (in)

## P83CE598FHB
designator U?
8-Bit Microcontroller with On-Chip CAN, with ROM
footprint SOT318-1_N (QFP, 80-Leads, Body 20x14mm, Pitch 0.8mm, IPC Medium Density)
footprint SOT318-1_L (QFP, 80-Leads, Body 20x14mm, Pitch 0.8mm, IPC High Density)
footprint SOT318-1_M (QFP, 80-Leads, Body 20x14mm, Pitch 0.8mm, IPC Low Density)
pins: 1 AVREF- (in), 2 AVREF+ (in), 3 AVSS (power), 4 AVDD (power), 5 P5.7/ADC7 (in), 6 P5.6/ADC6 (in), 7 P5.5/ADC5 (in), 8 P5.4/ADC4 (in), 9 P5.3/ADC3 (in), 10 P5.2/ADC2 (in), 11 P5.1/ADC1 (in), 12 P5.0/ADC0 (in), 13 VSS1 (power), 14 VDD1 (power), 15 STADC (in), 16 ~{PWM}0 (out), 17 ~{PWM}1 (out), 18 ~{EW} (in), 19 P4.0/CMSR0 (io), 20 P4.1/CMSR1 (io), 21 P4.2/CMSR2 (io), 22 P4.3/CMSR3 (io), 23 NC, 24 P4.4/CMSR4 (io), 25 P4.5/CMSR5 (io), 26 P4.6/CMT0 (io), 27 P4.7/CMT1 (io), 28 VDD2 (power), 29 VSS2 (power), 30 RST (io), 31 P1.0/CT0I/INT2 (io), 32 P1.1/CT1I/INT3 (io), 33 P1.2/CT2I/INT4 (io), 34 P1.3/CT3I/INT5 (io), 35 P1.4/T2 (io), 36 P1.5/RT2 (io), 37 CVSS (power), 38 P1.6/CTX0 (io), 39 P1.7/CTX1 (io), 40 CVDD (power), 41 P3.0/RXD (io), 42 P3.1/TXD (io), 43 P3.2/~{INT}0 (io), 44 P3.3/~{INT}1 (io), 45 P3.4/T0 (io), 46 P3.5/T1 (io), 47 P3.6/~{WR} (io), 48 P3.7/~{RD} (io), 49 NC, 50 NC, 51 XTAL2 (out), 52 XTAL1 (in), 53 VDD3 (power), 54 VSS3 (power), 55 P2.0/A08 (io), 56 P2.1/A09 (io), 57 P2.2/A10 (io), 58 P2.3/A11 (io), 59 P2.4/A12 (io), 60 P2.5/A13 (io), 61 P2.6/A14 (io), 62 P2.7/A15 (io), 63 ~{PSEN} (out), 64 ALE (out), 65 ~{EA} (in), 66 NC, 67 NC, 68 P0.7/AD7 (io), 69 P0.6/AD6 (io), 70 P0.5/AD5 (io), 71 P0.4/AD4 (io), 72 P0.3/AD3 (io), 73 P0.2/AD2 (io), 74 P0.1/AD1 (io), 75 P0.0/AD0 (io), 76 VDD4 (power), 77 VSS4 (power), 78 REF (io), 79 CRX1 (in), 80 CRX0 (in)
